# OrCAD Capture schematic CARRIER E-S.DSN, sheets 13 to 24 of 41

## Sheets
13 B4B11
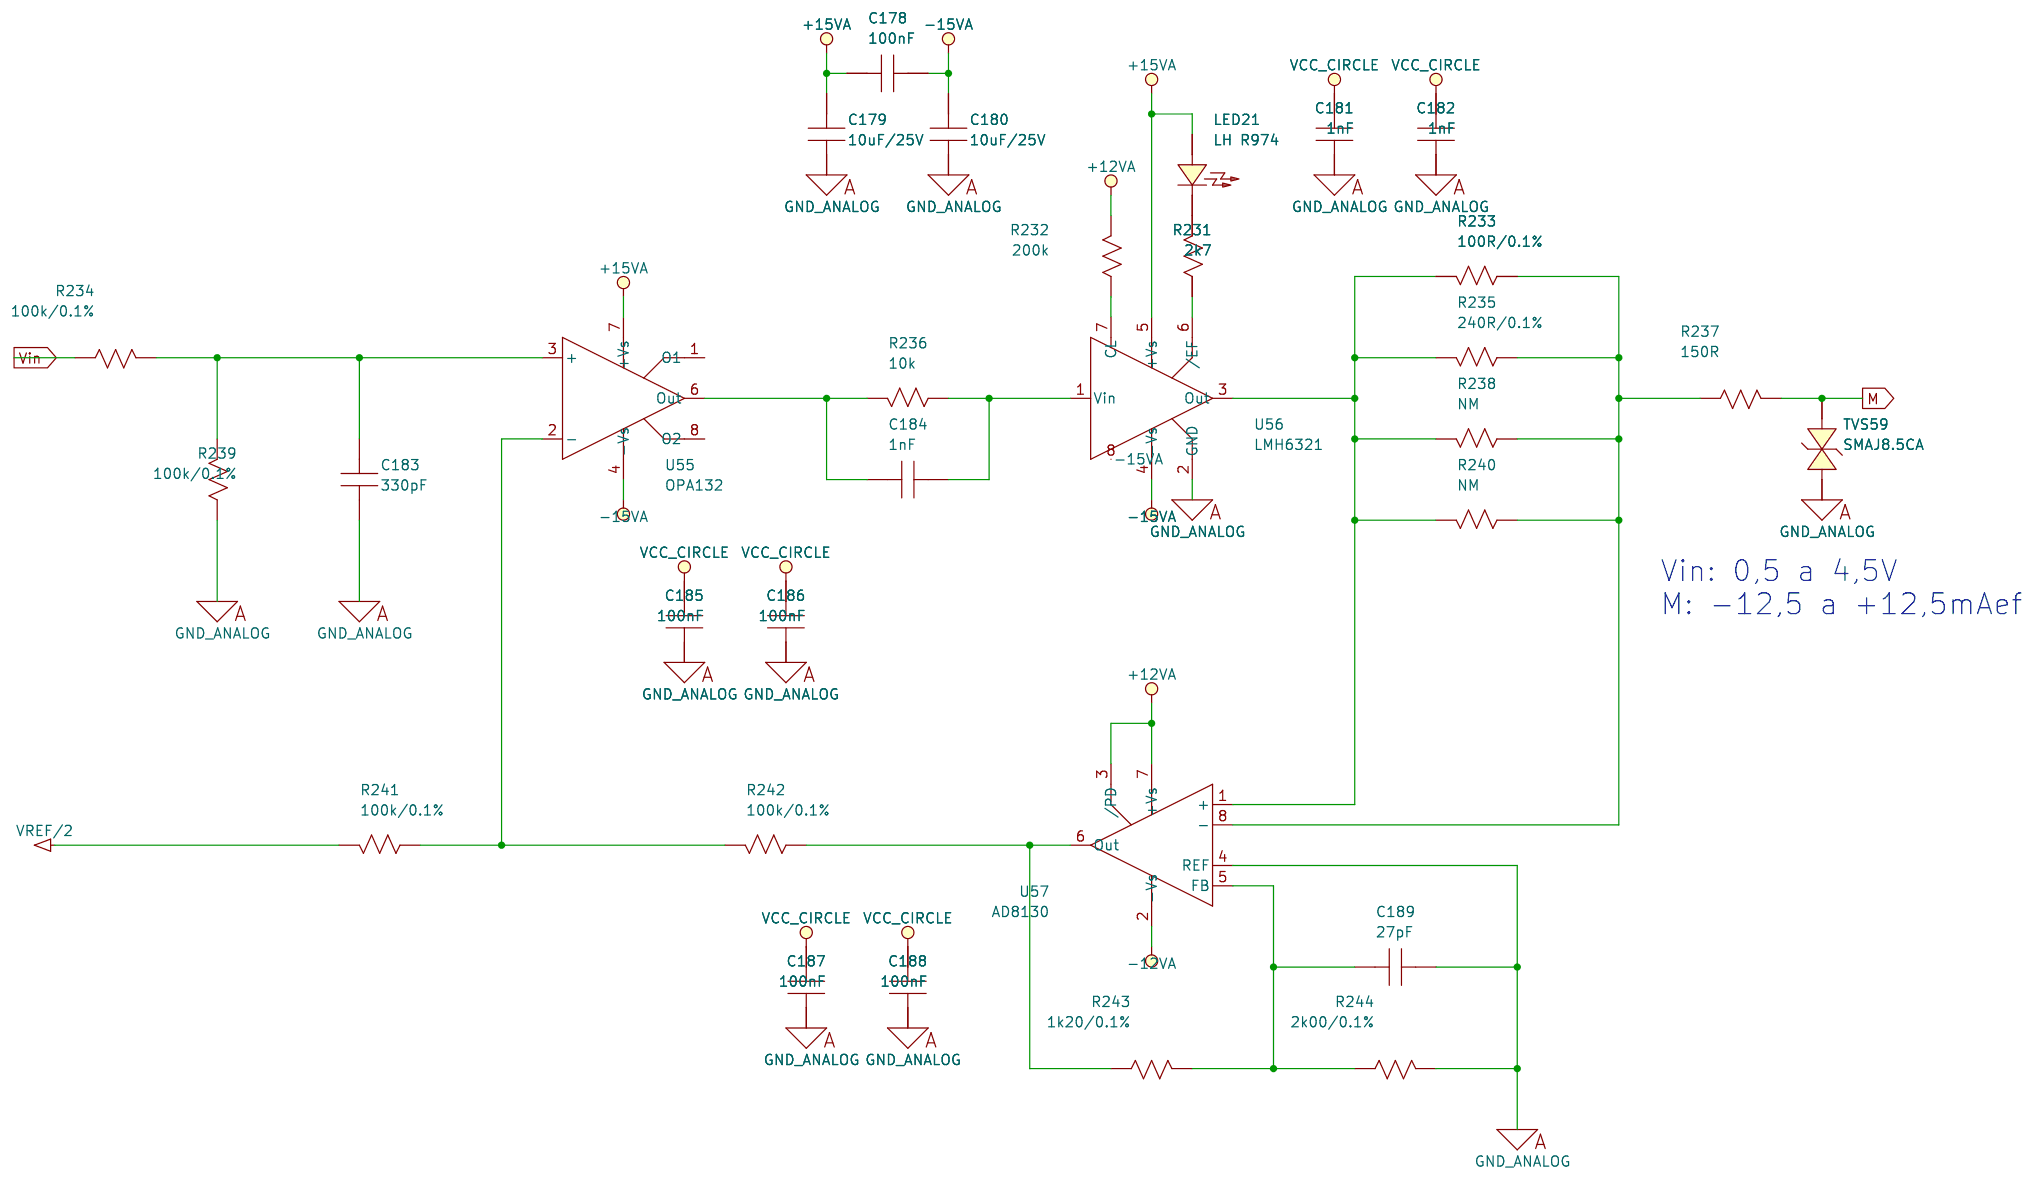
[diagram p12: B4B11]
14 B4B13
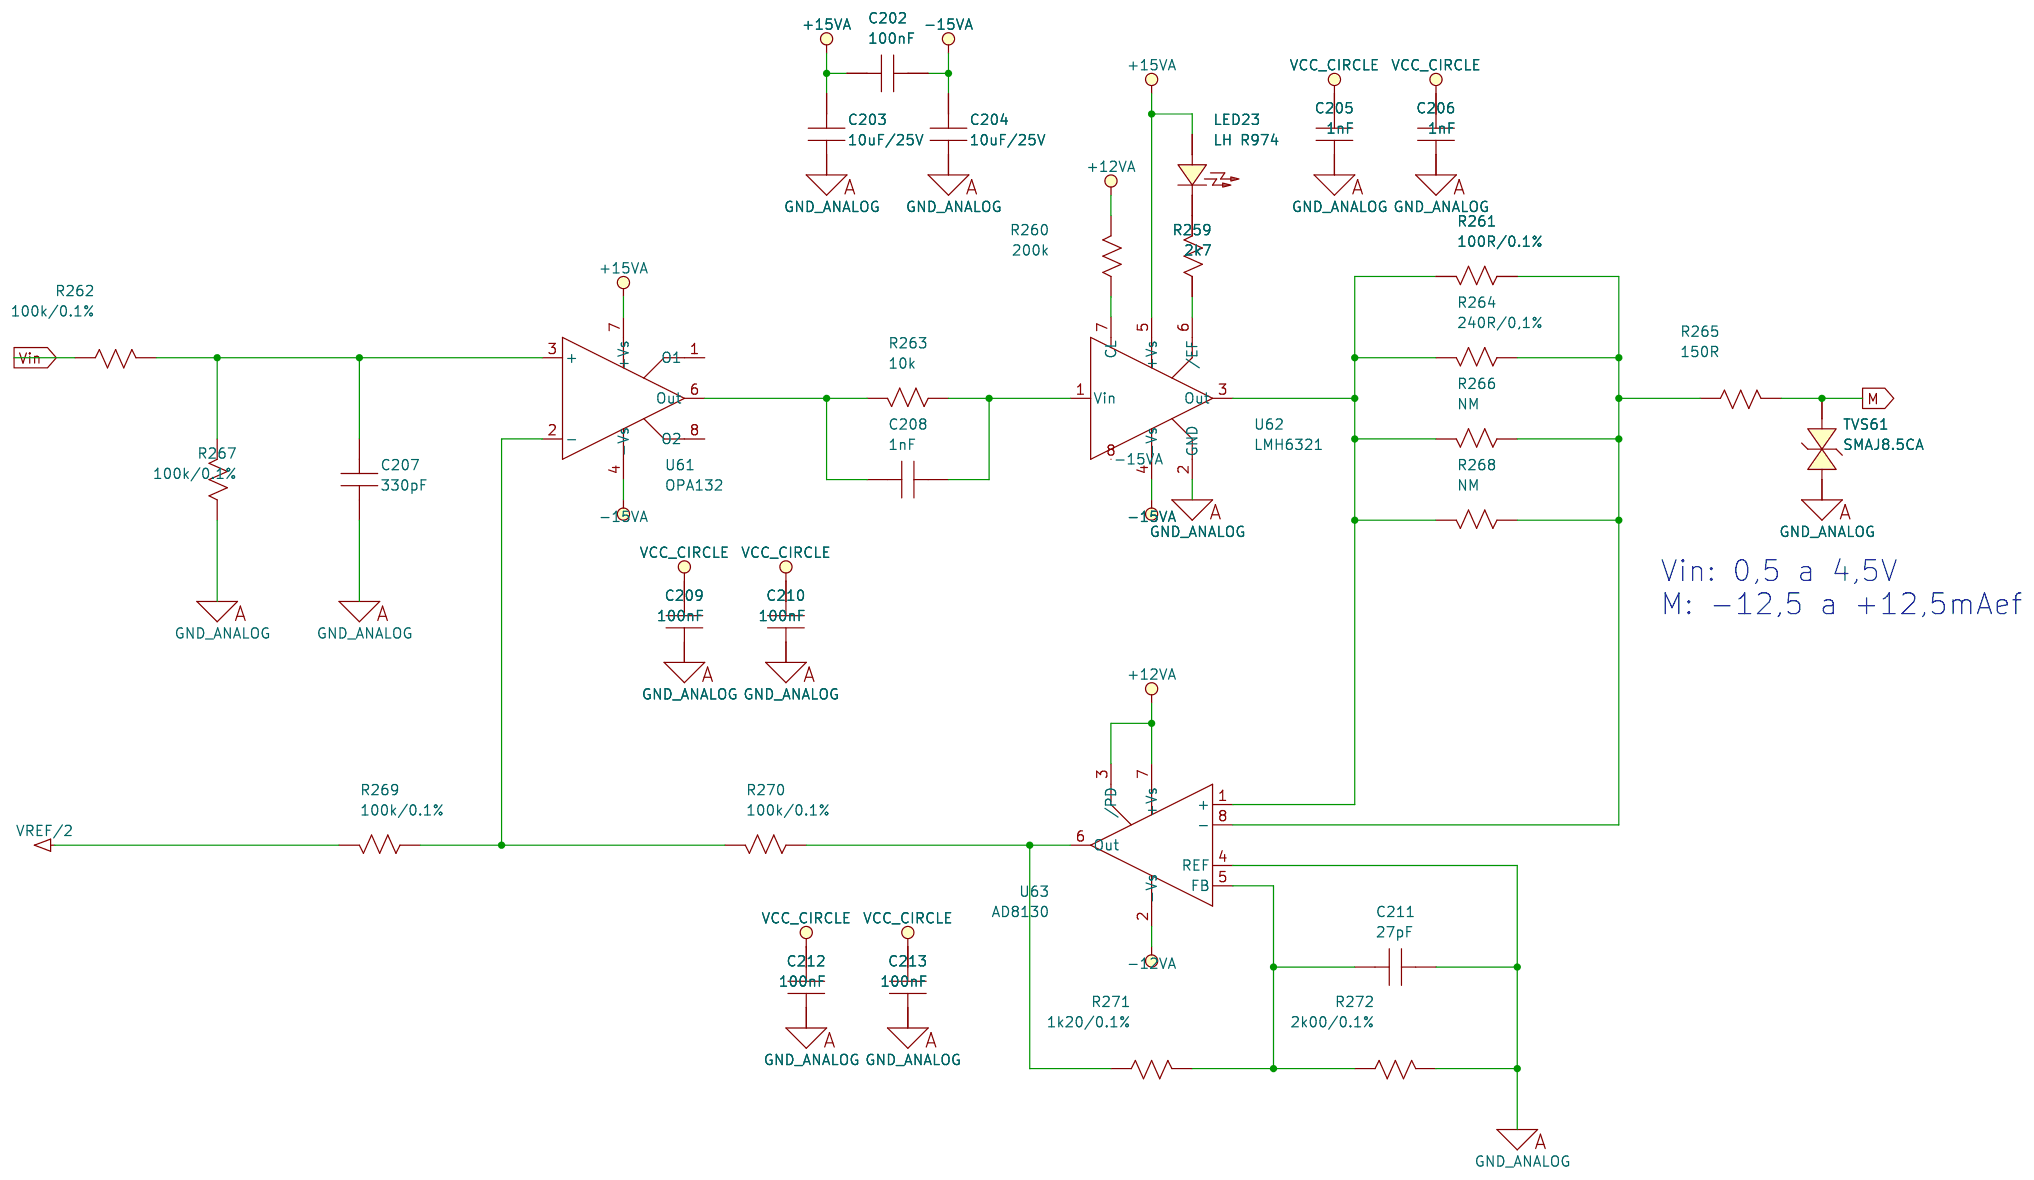
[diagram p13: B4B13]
15 B4B08
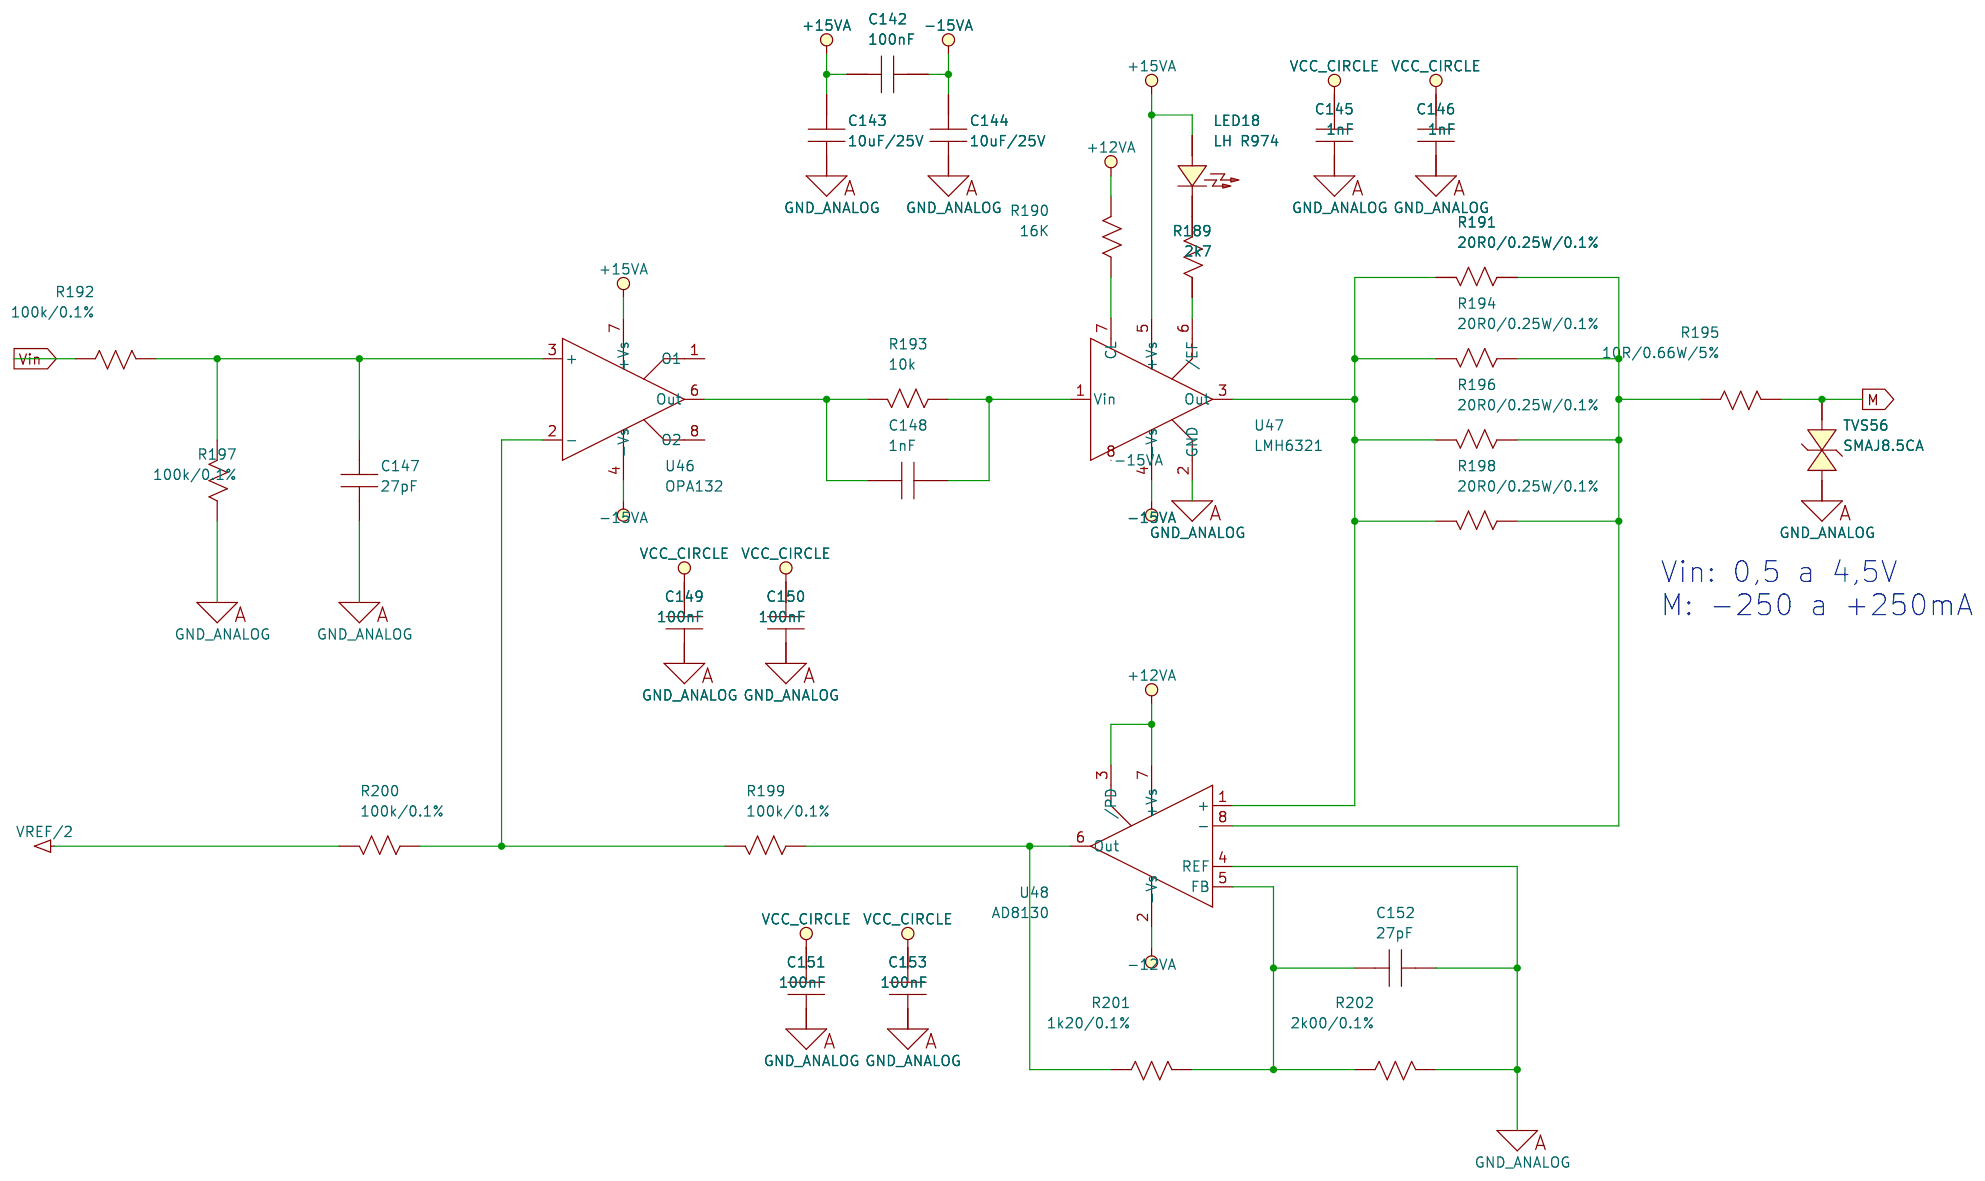
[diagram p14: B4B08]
16 B4B15
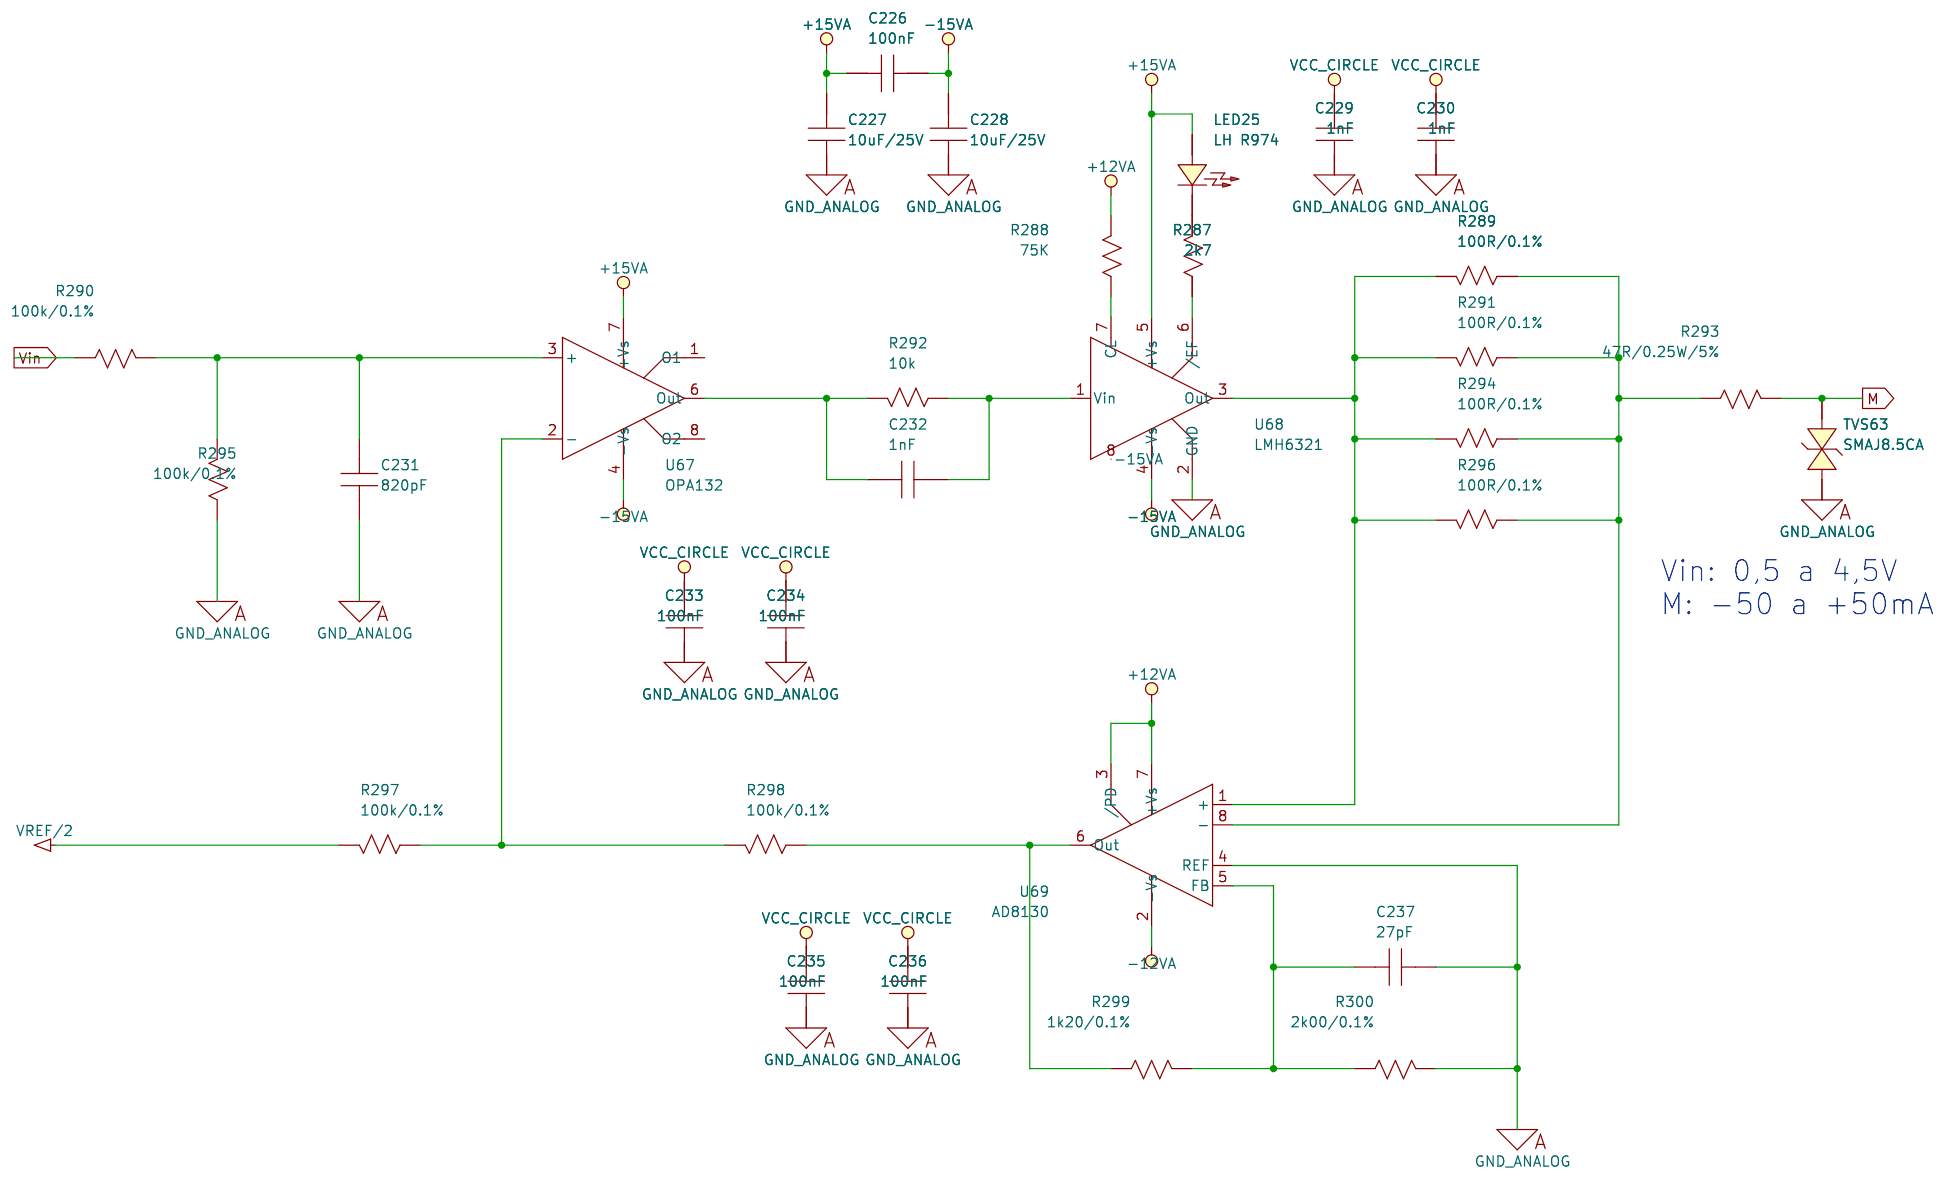
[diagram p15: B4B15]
17 B4B14
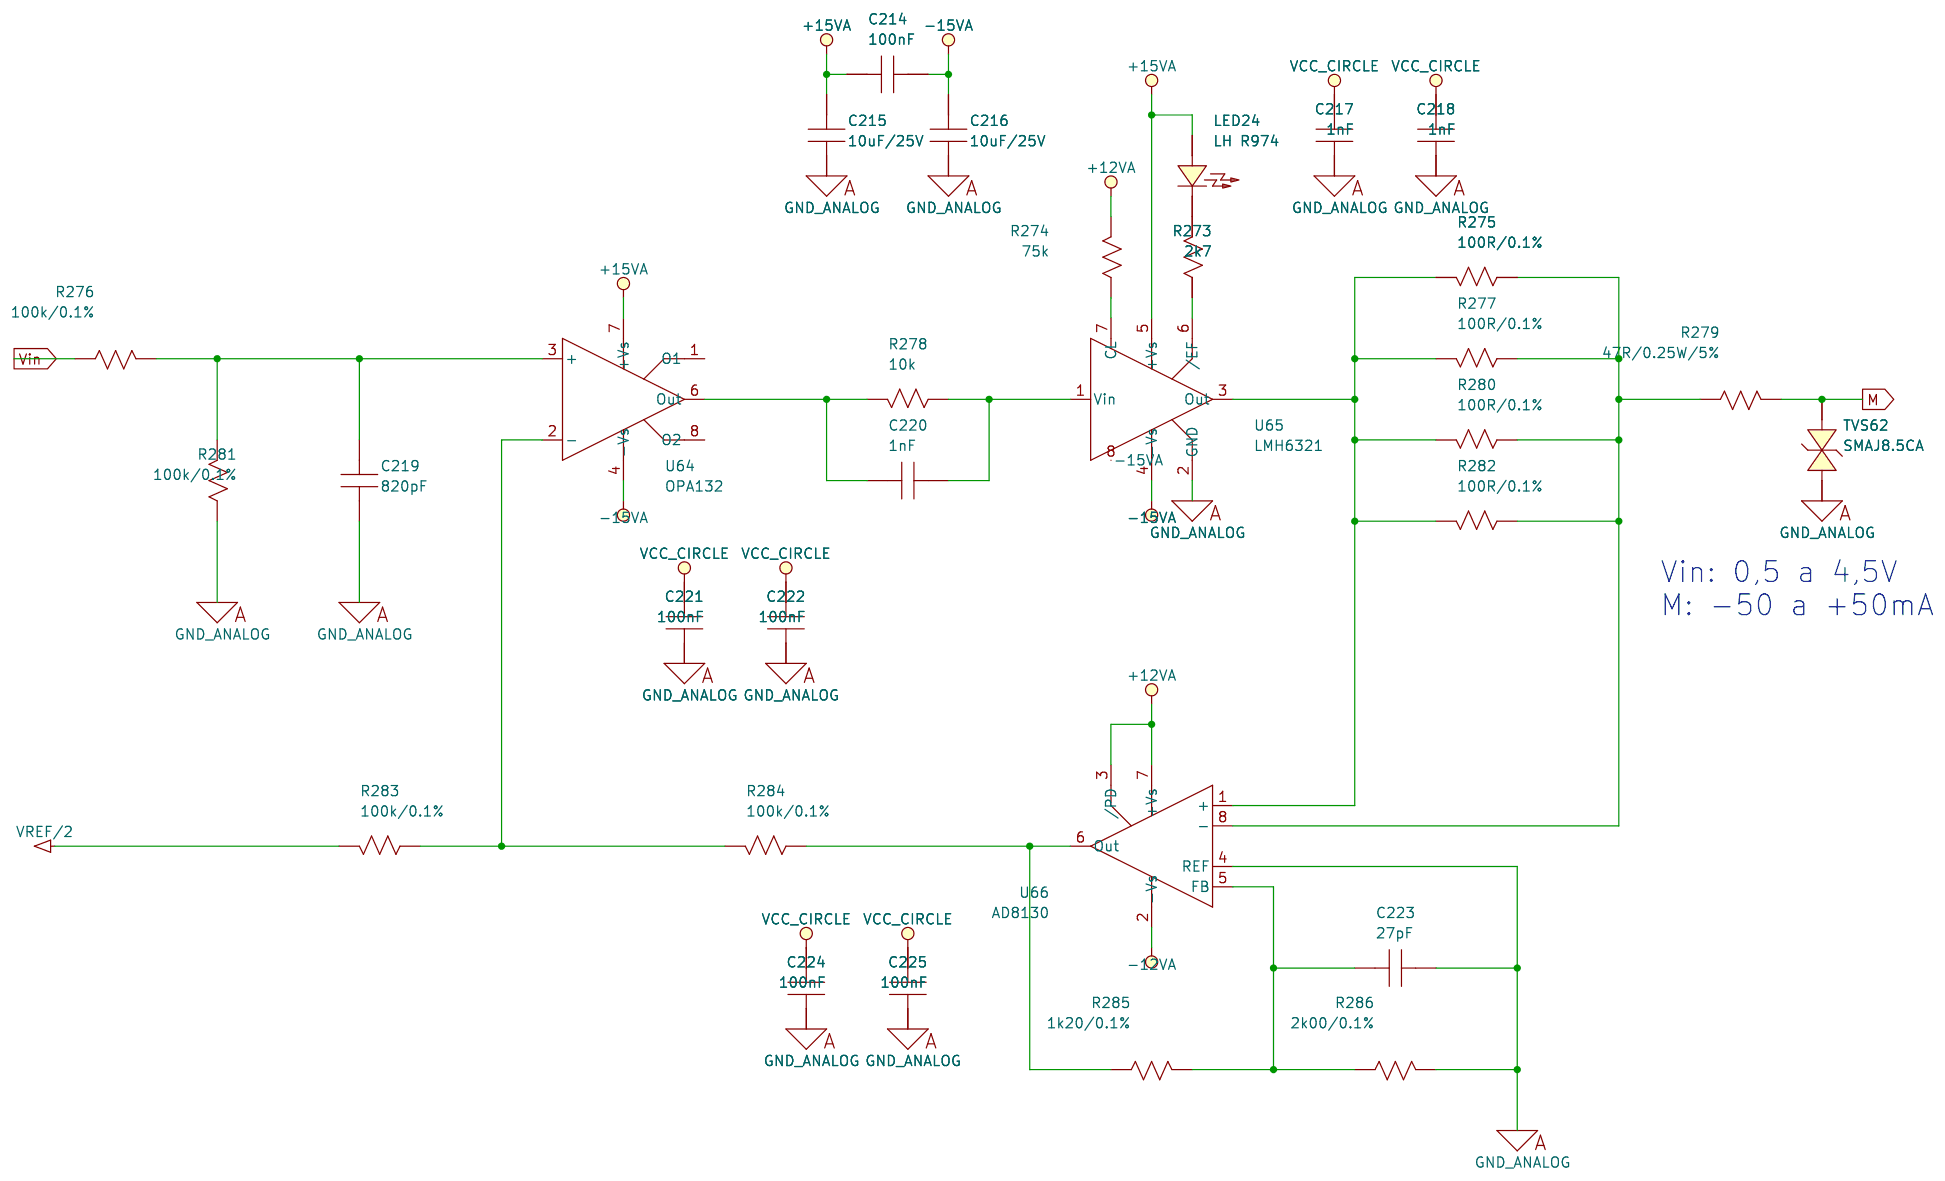
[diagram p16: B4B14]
18 B4B21
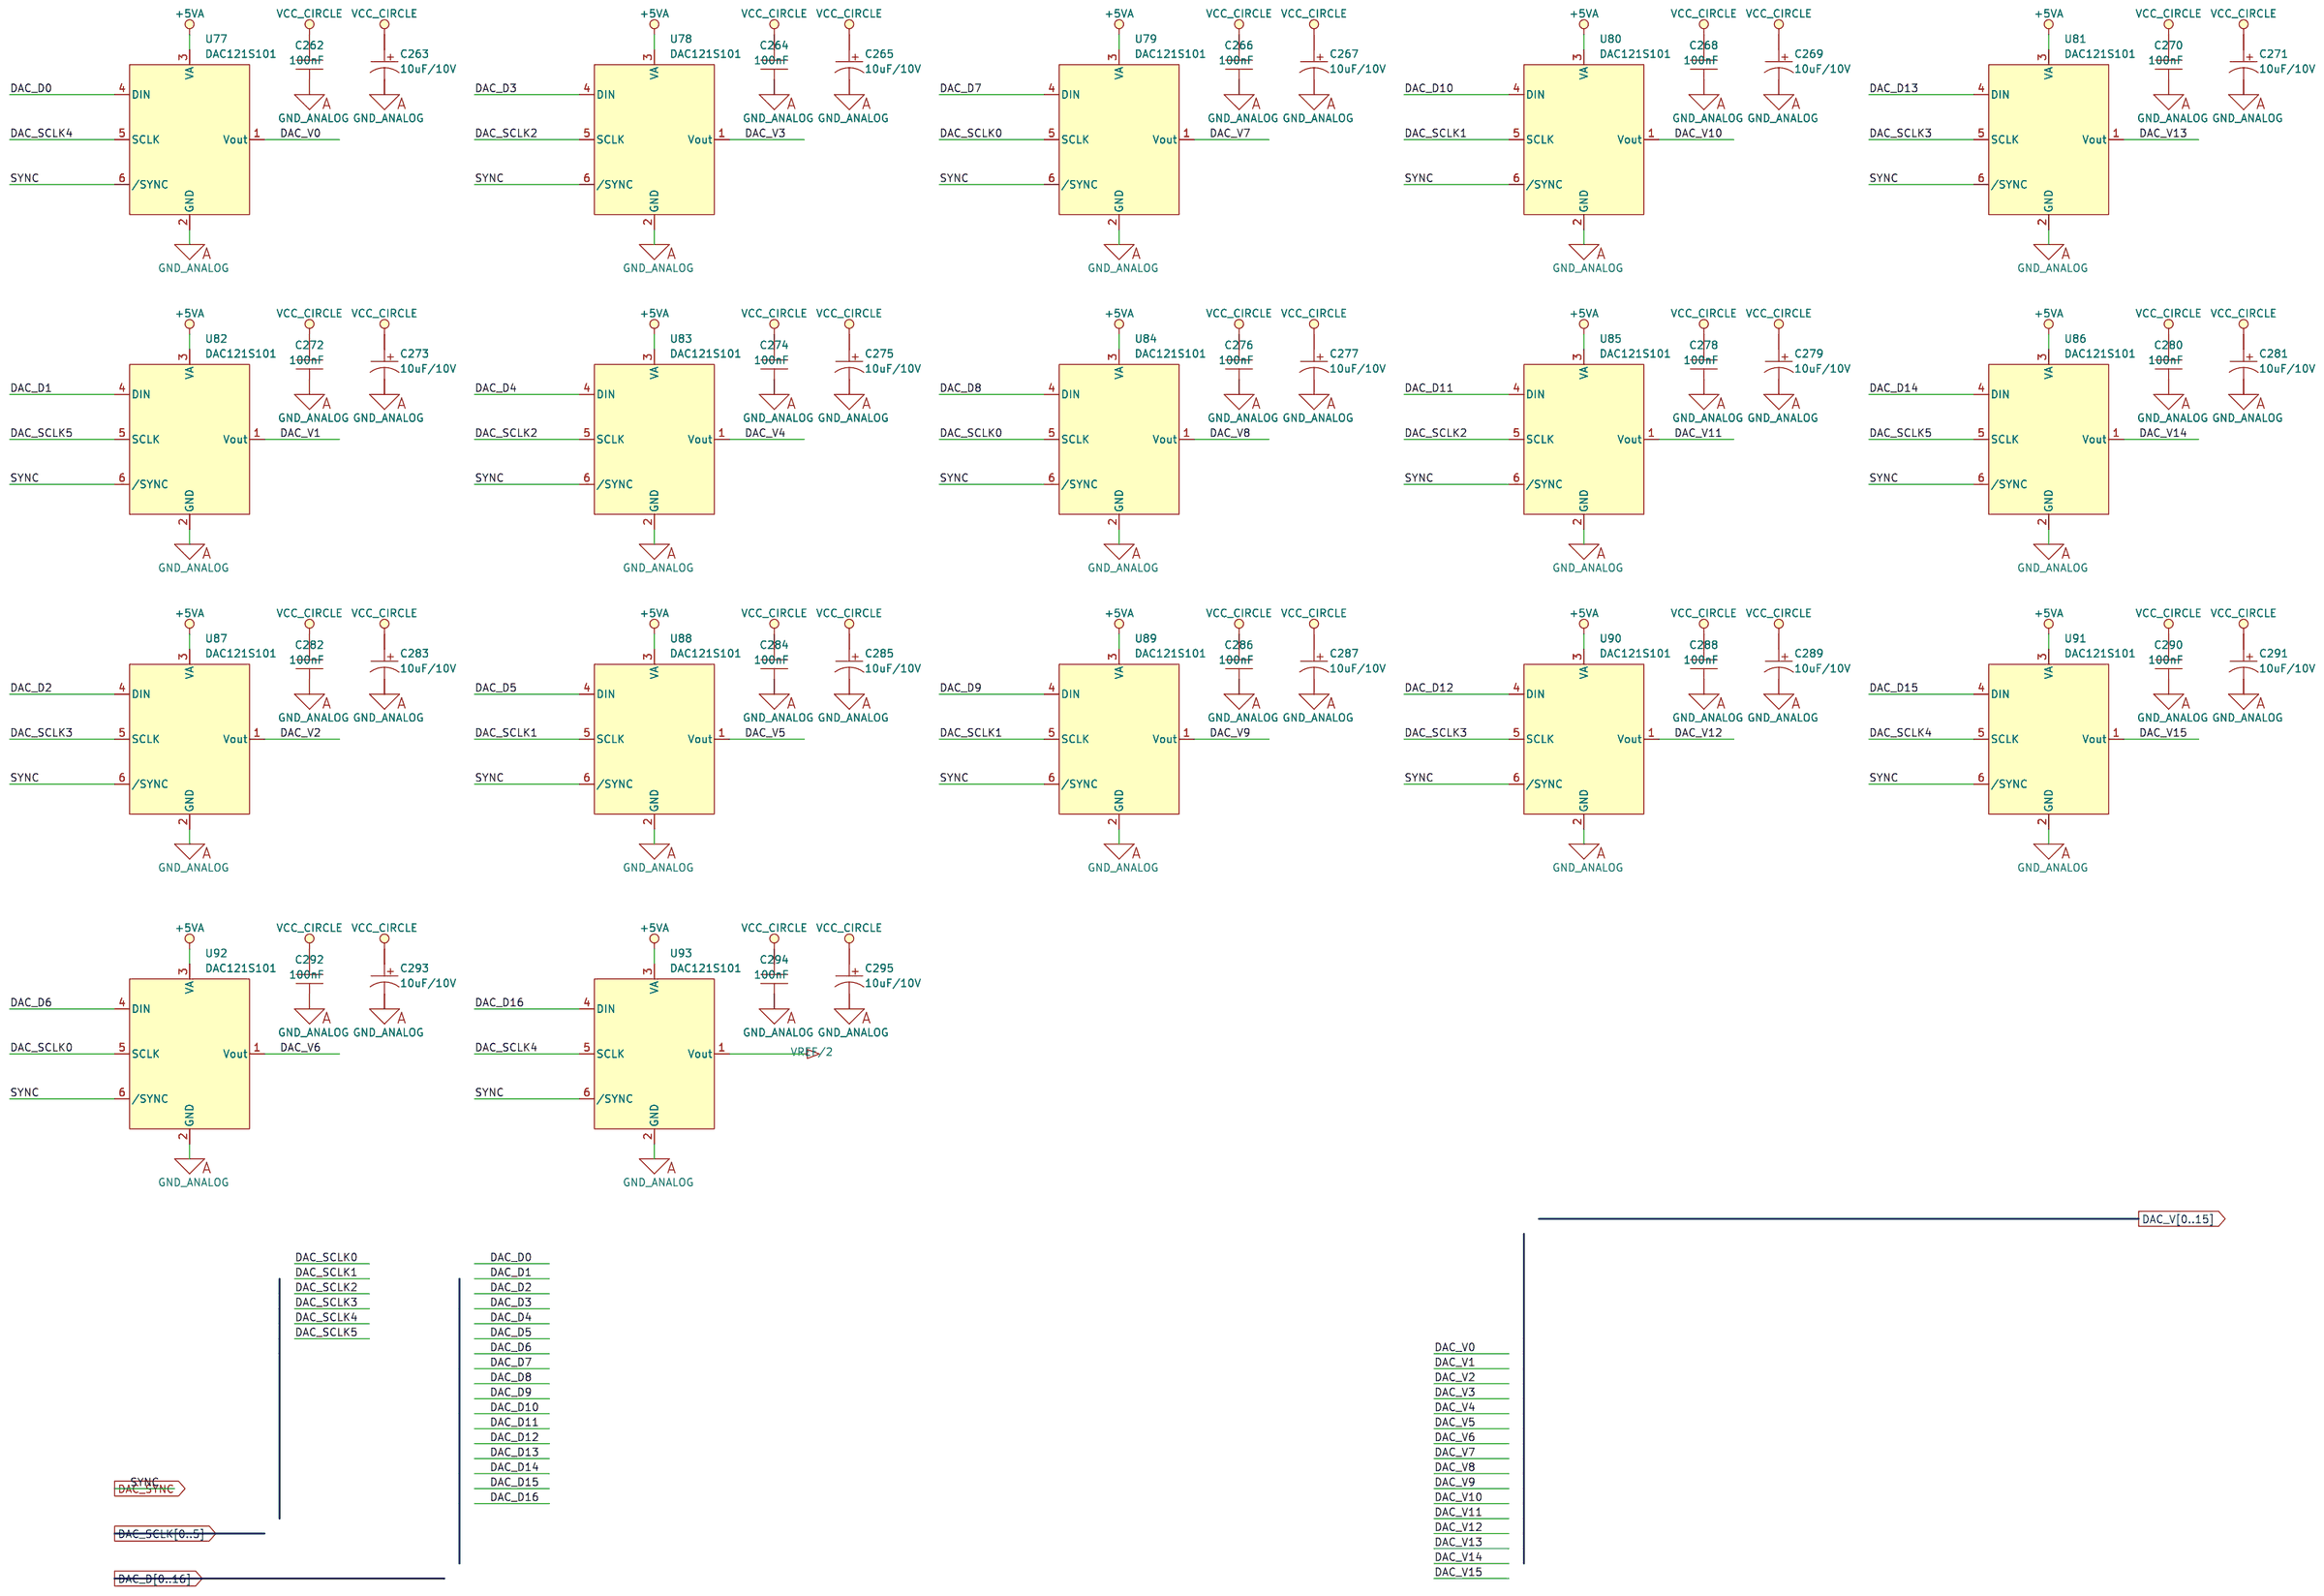
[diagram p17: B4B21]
19 B4B16
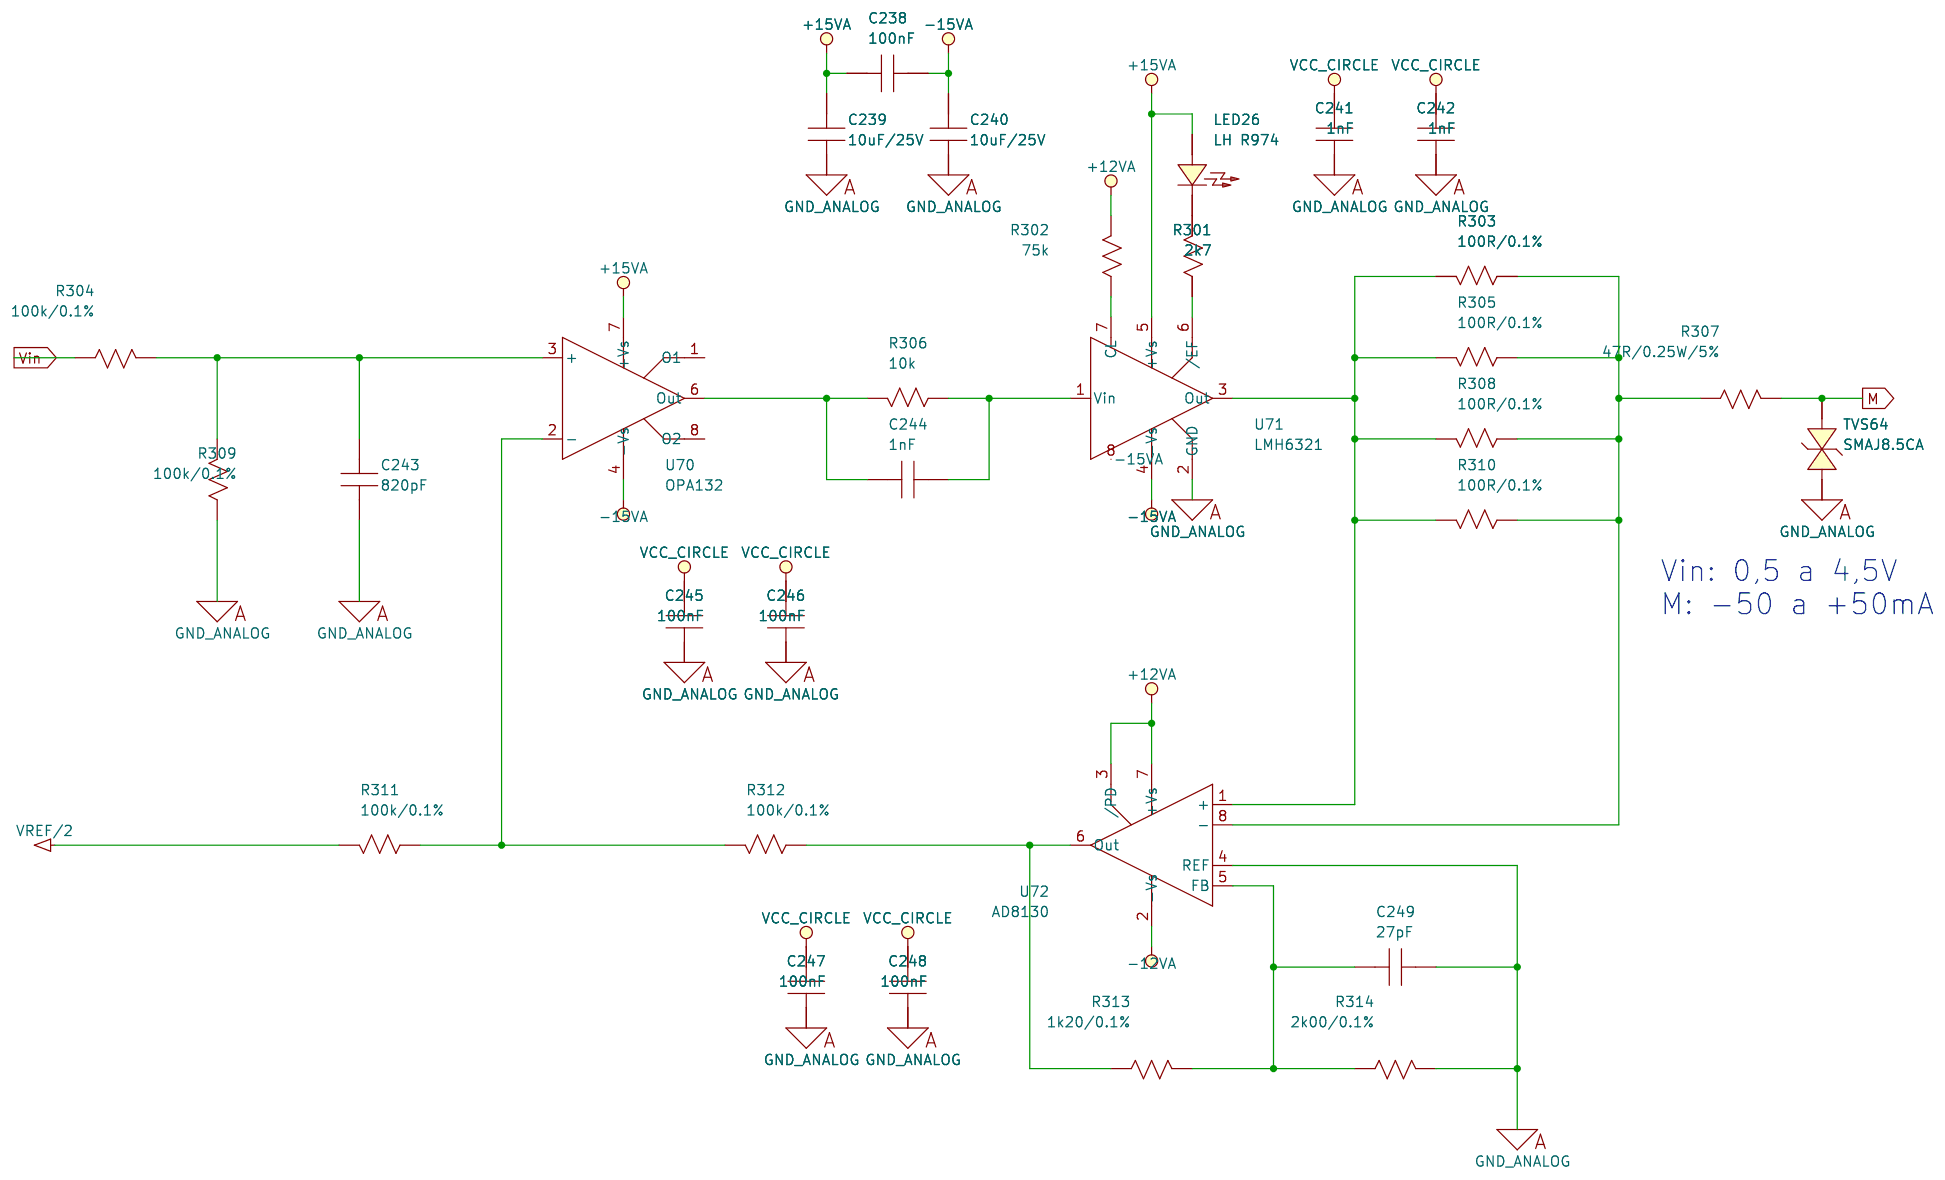
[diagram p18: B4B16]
20 B4B12
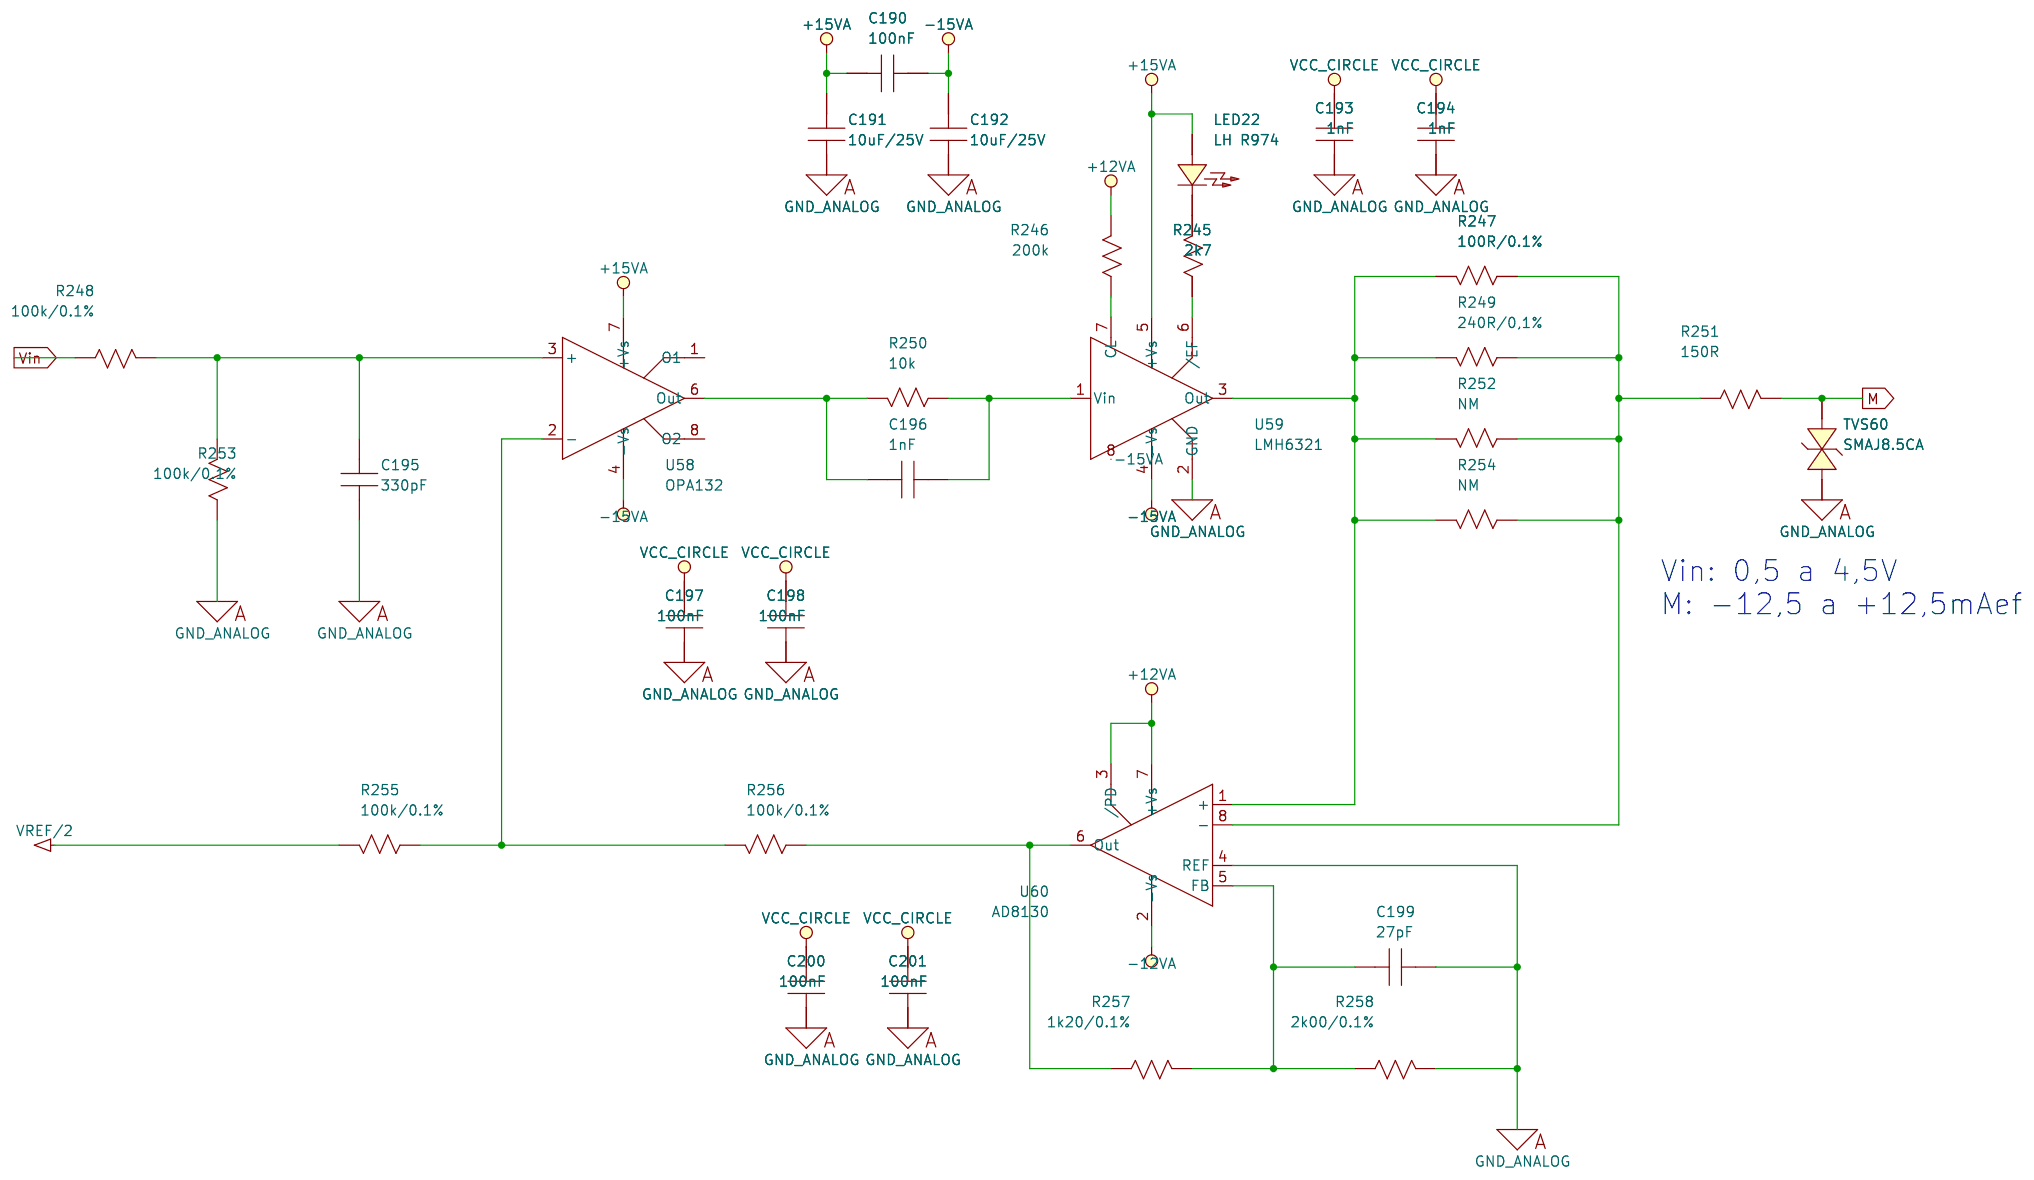
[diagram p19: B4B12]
21 B4B09
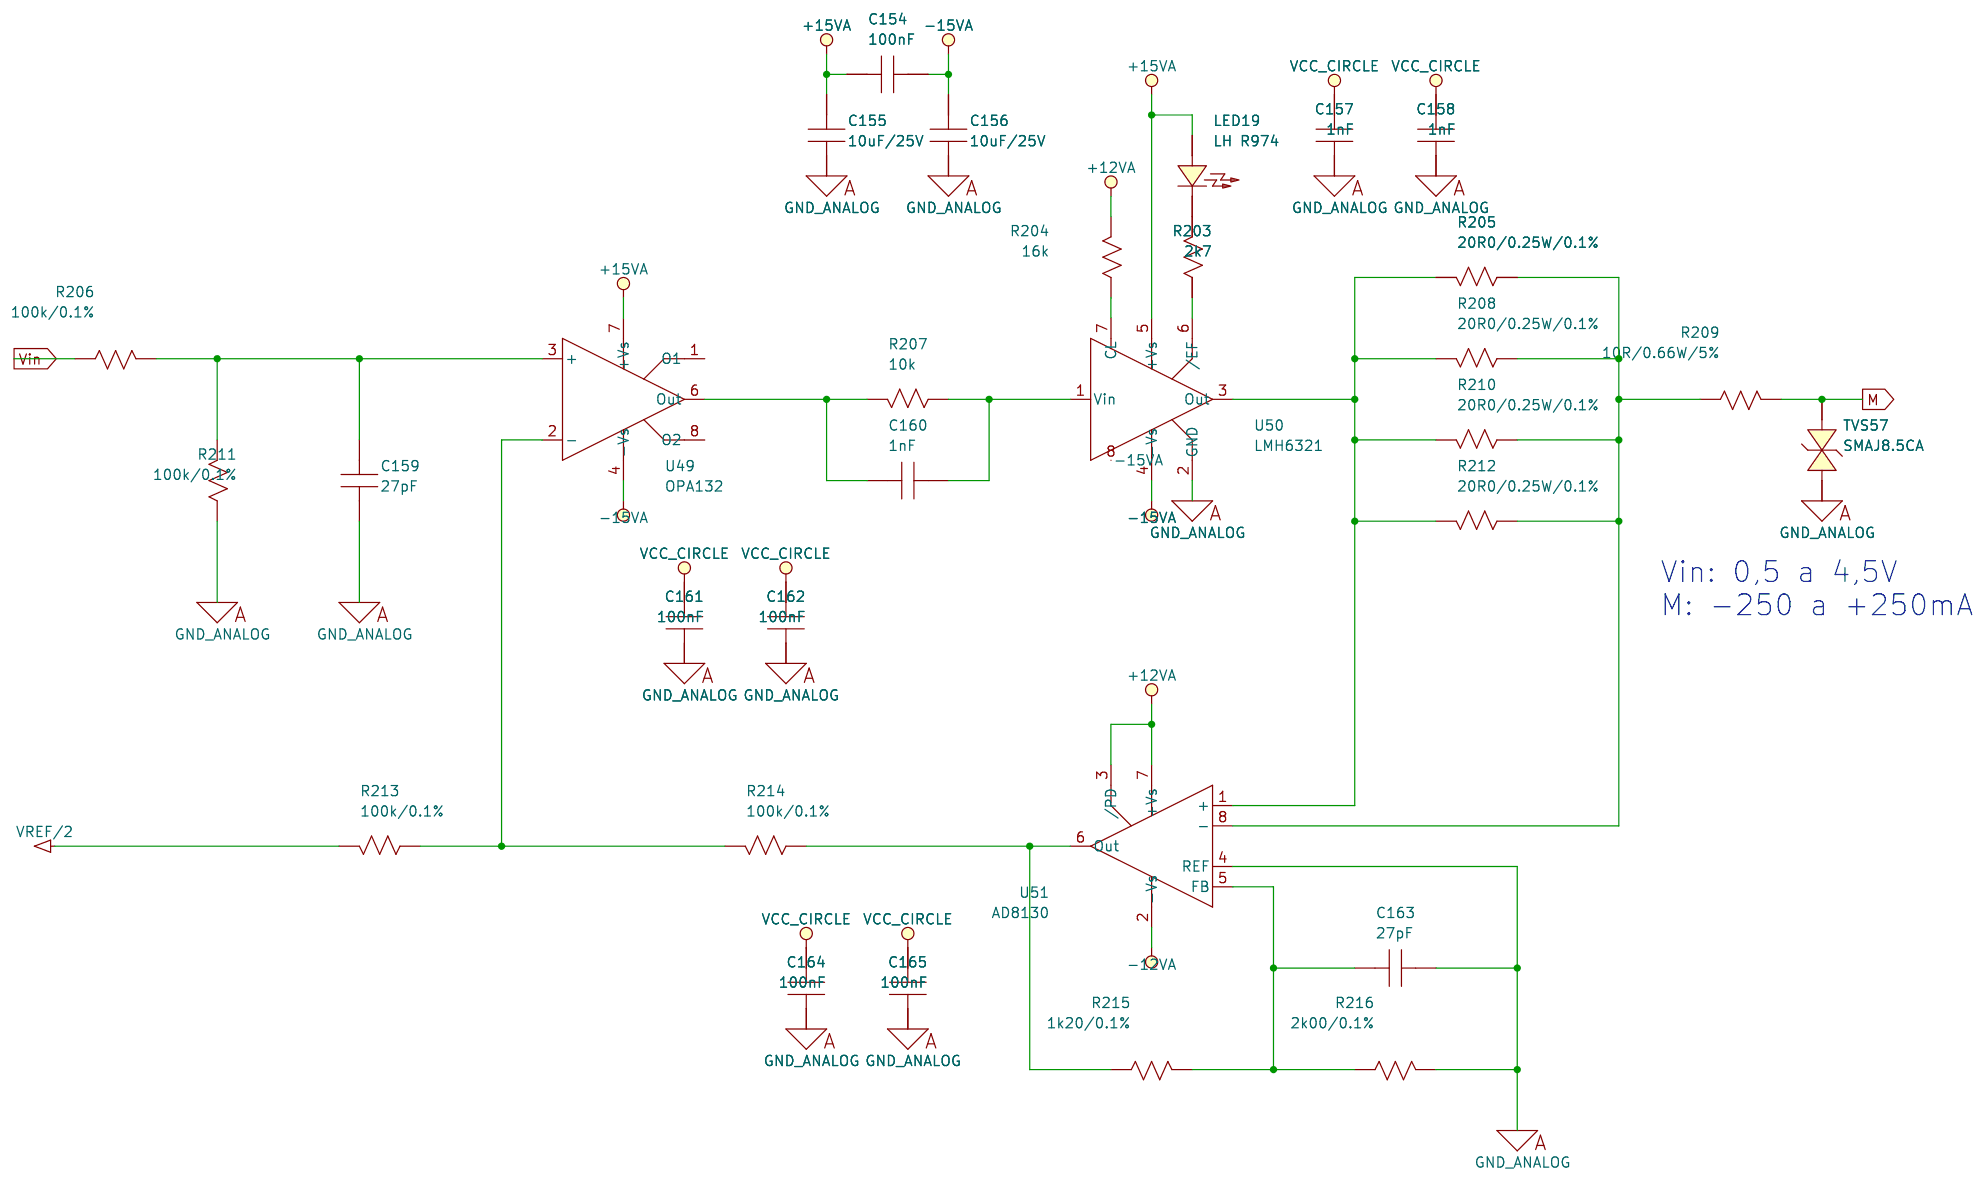
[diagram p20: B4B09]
22 B4B01
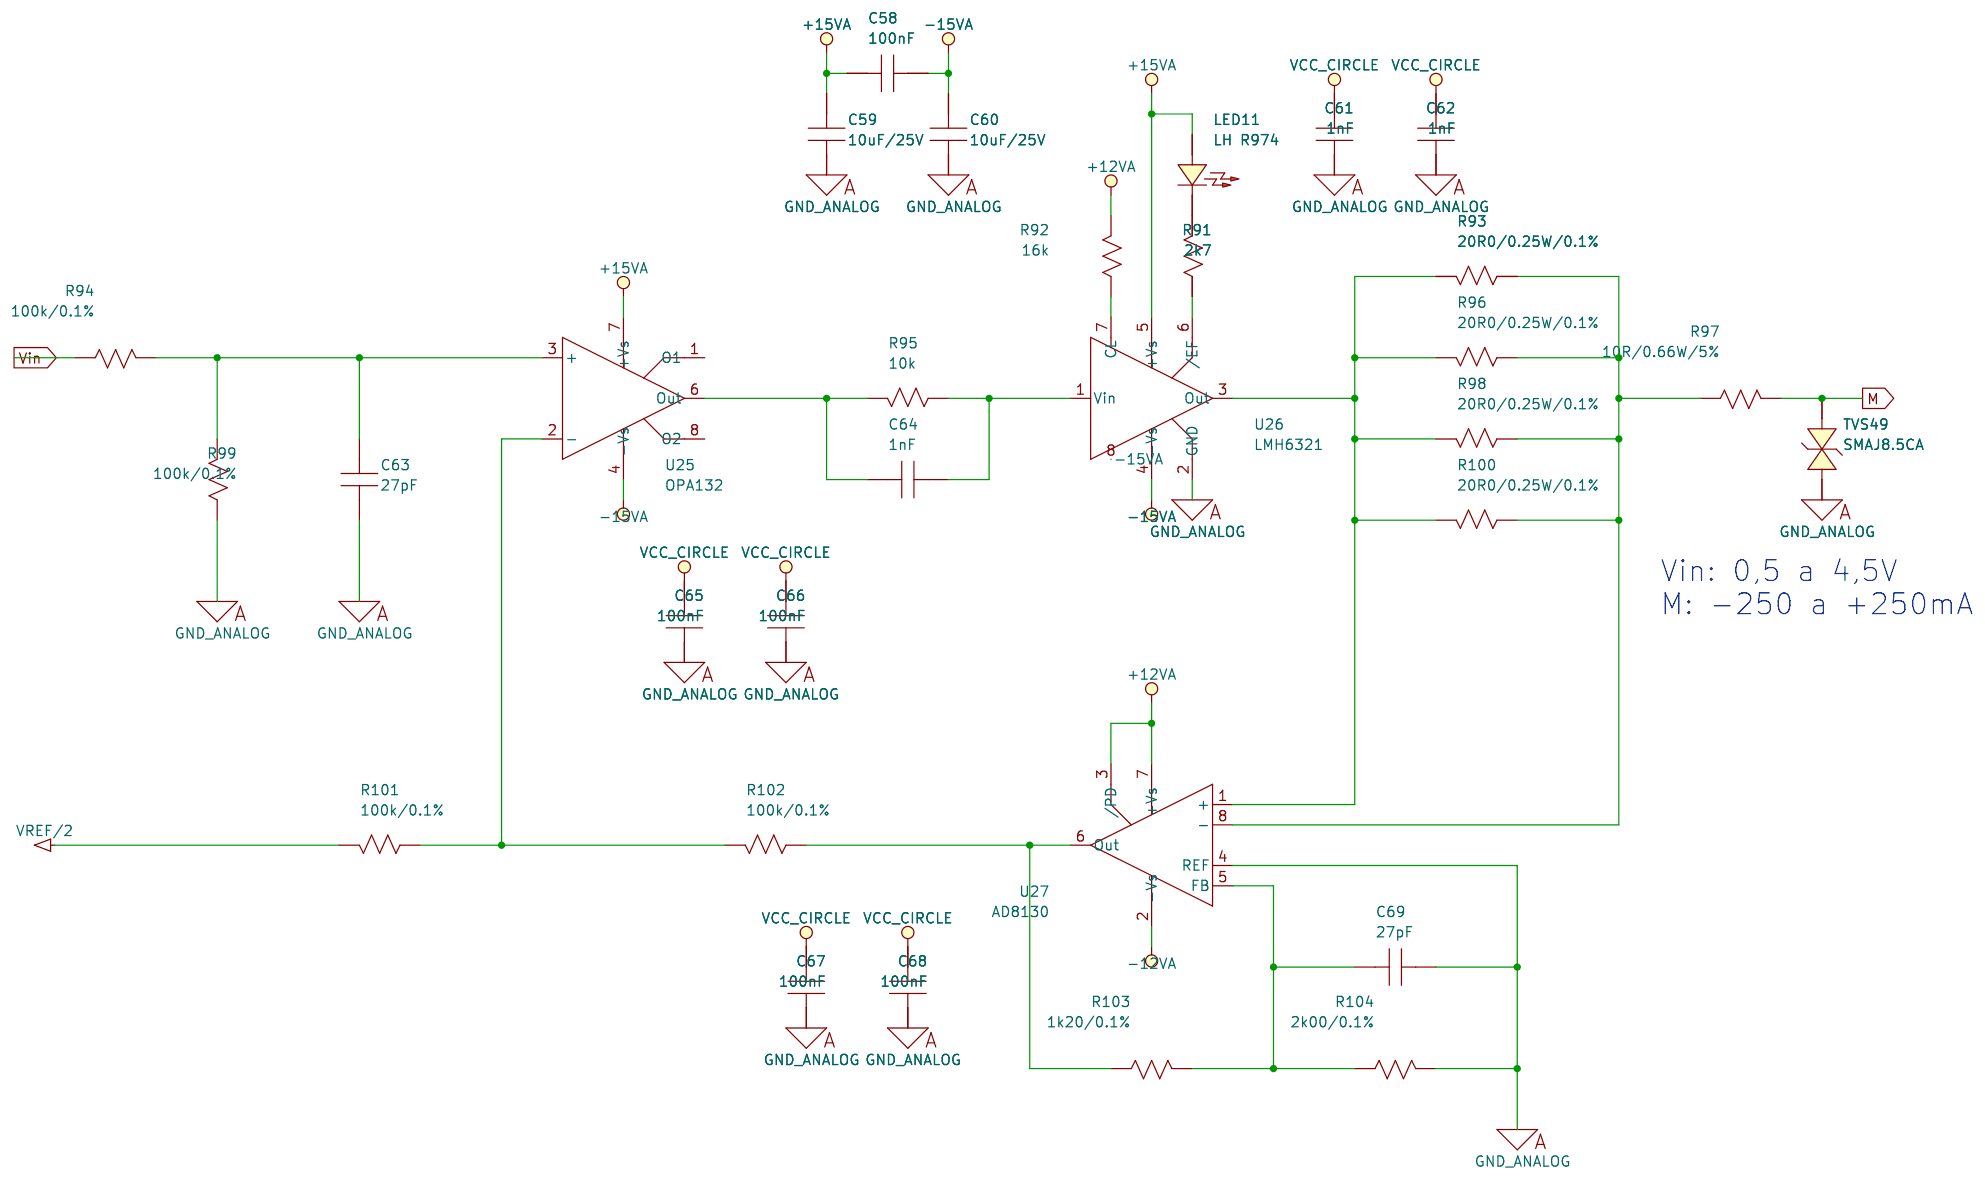
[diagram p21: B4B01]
23 B1: size A4; block Alimentacion
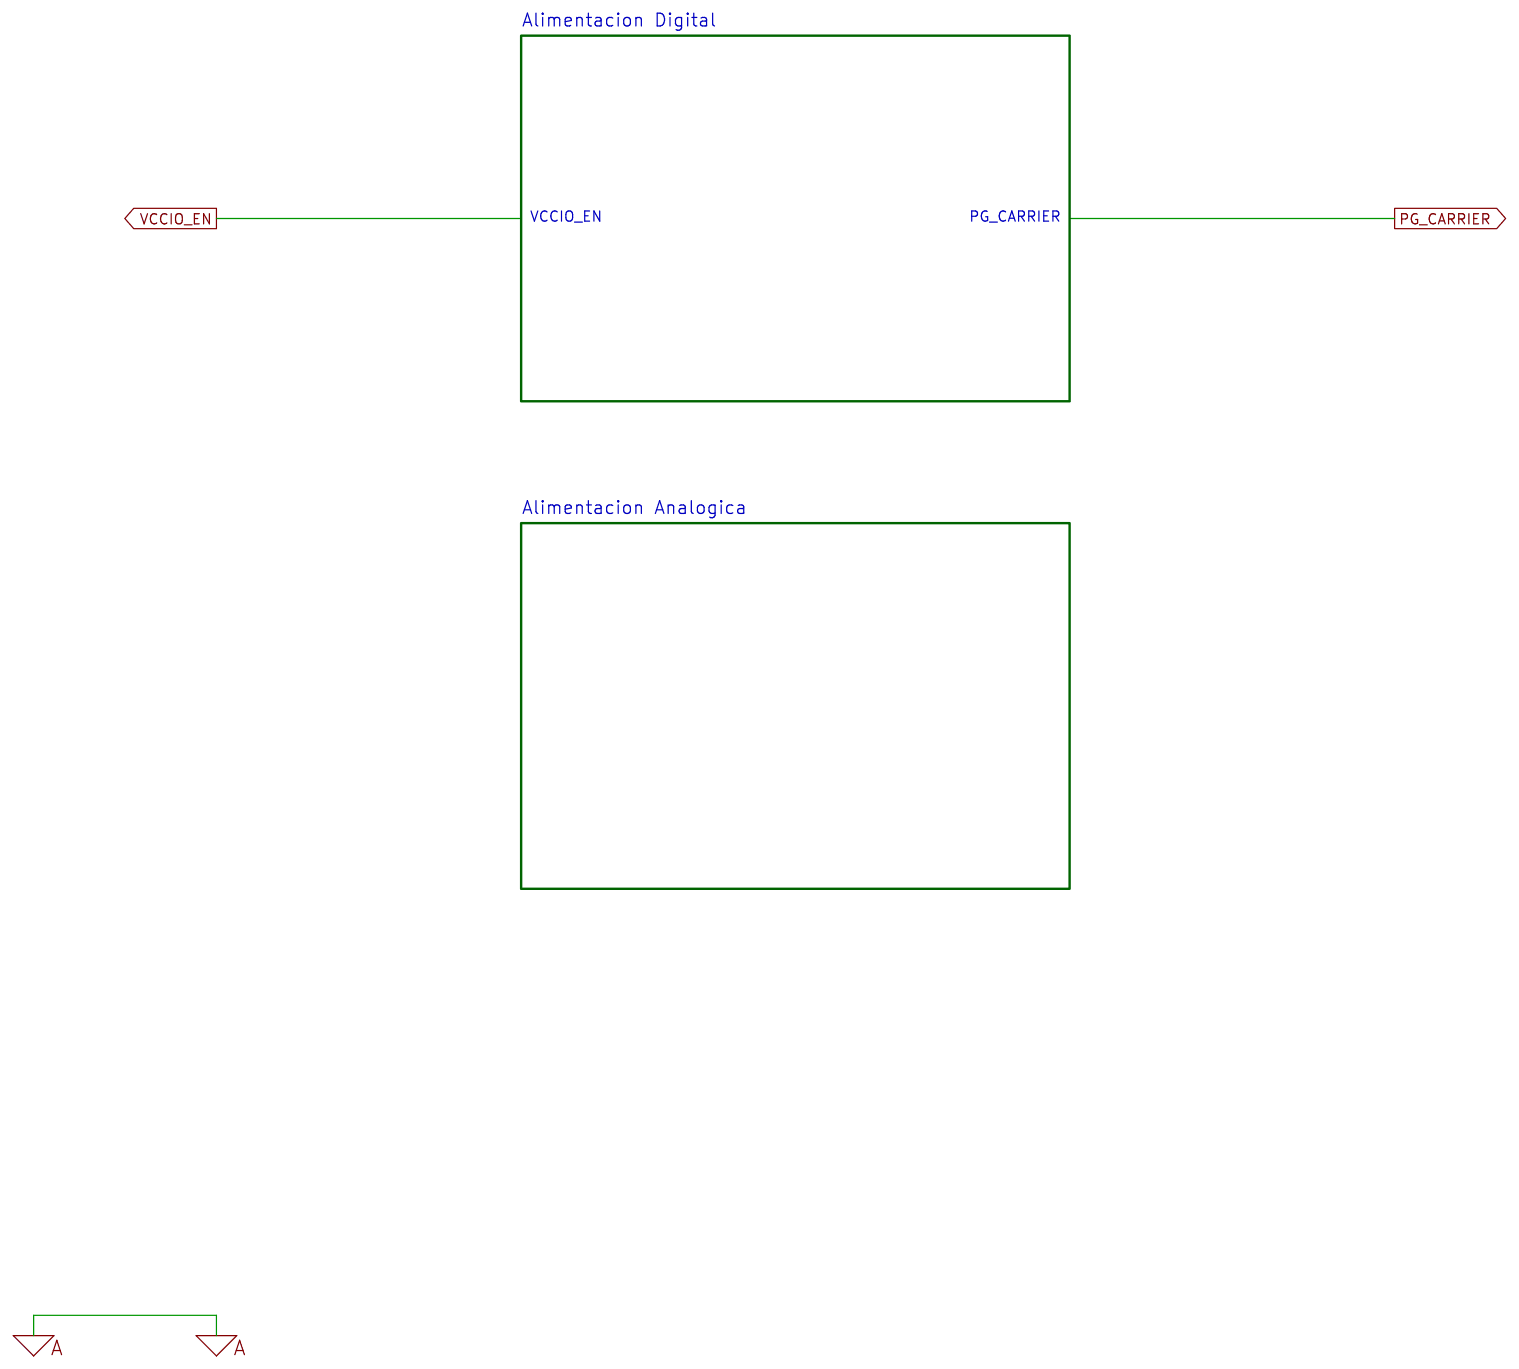
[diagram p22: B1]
24 B1B2: size A4; block Alimentacion/Alimentacion Analogica
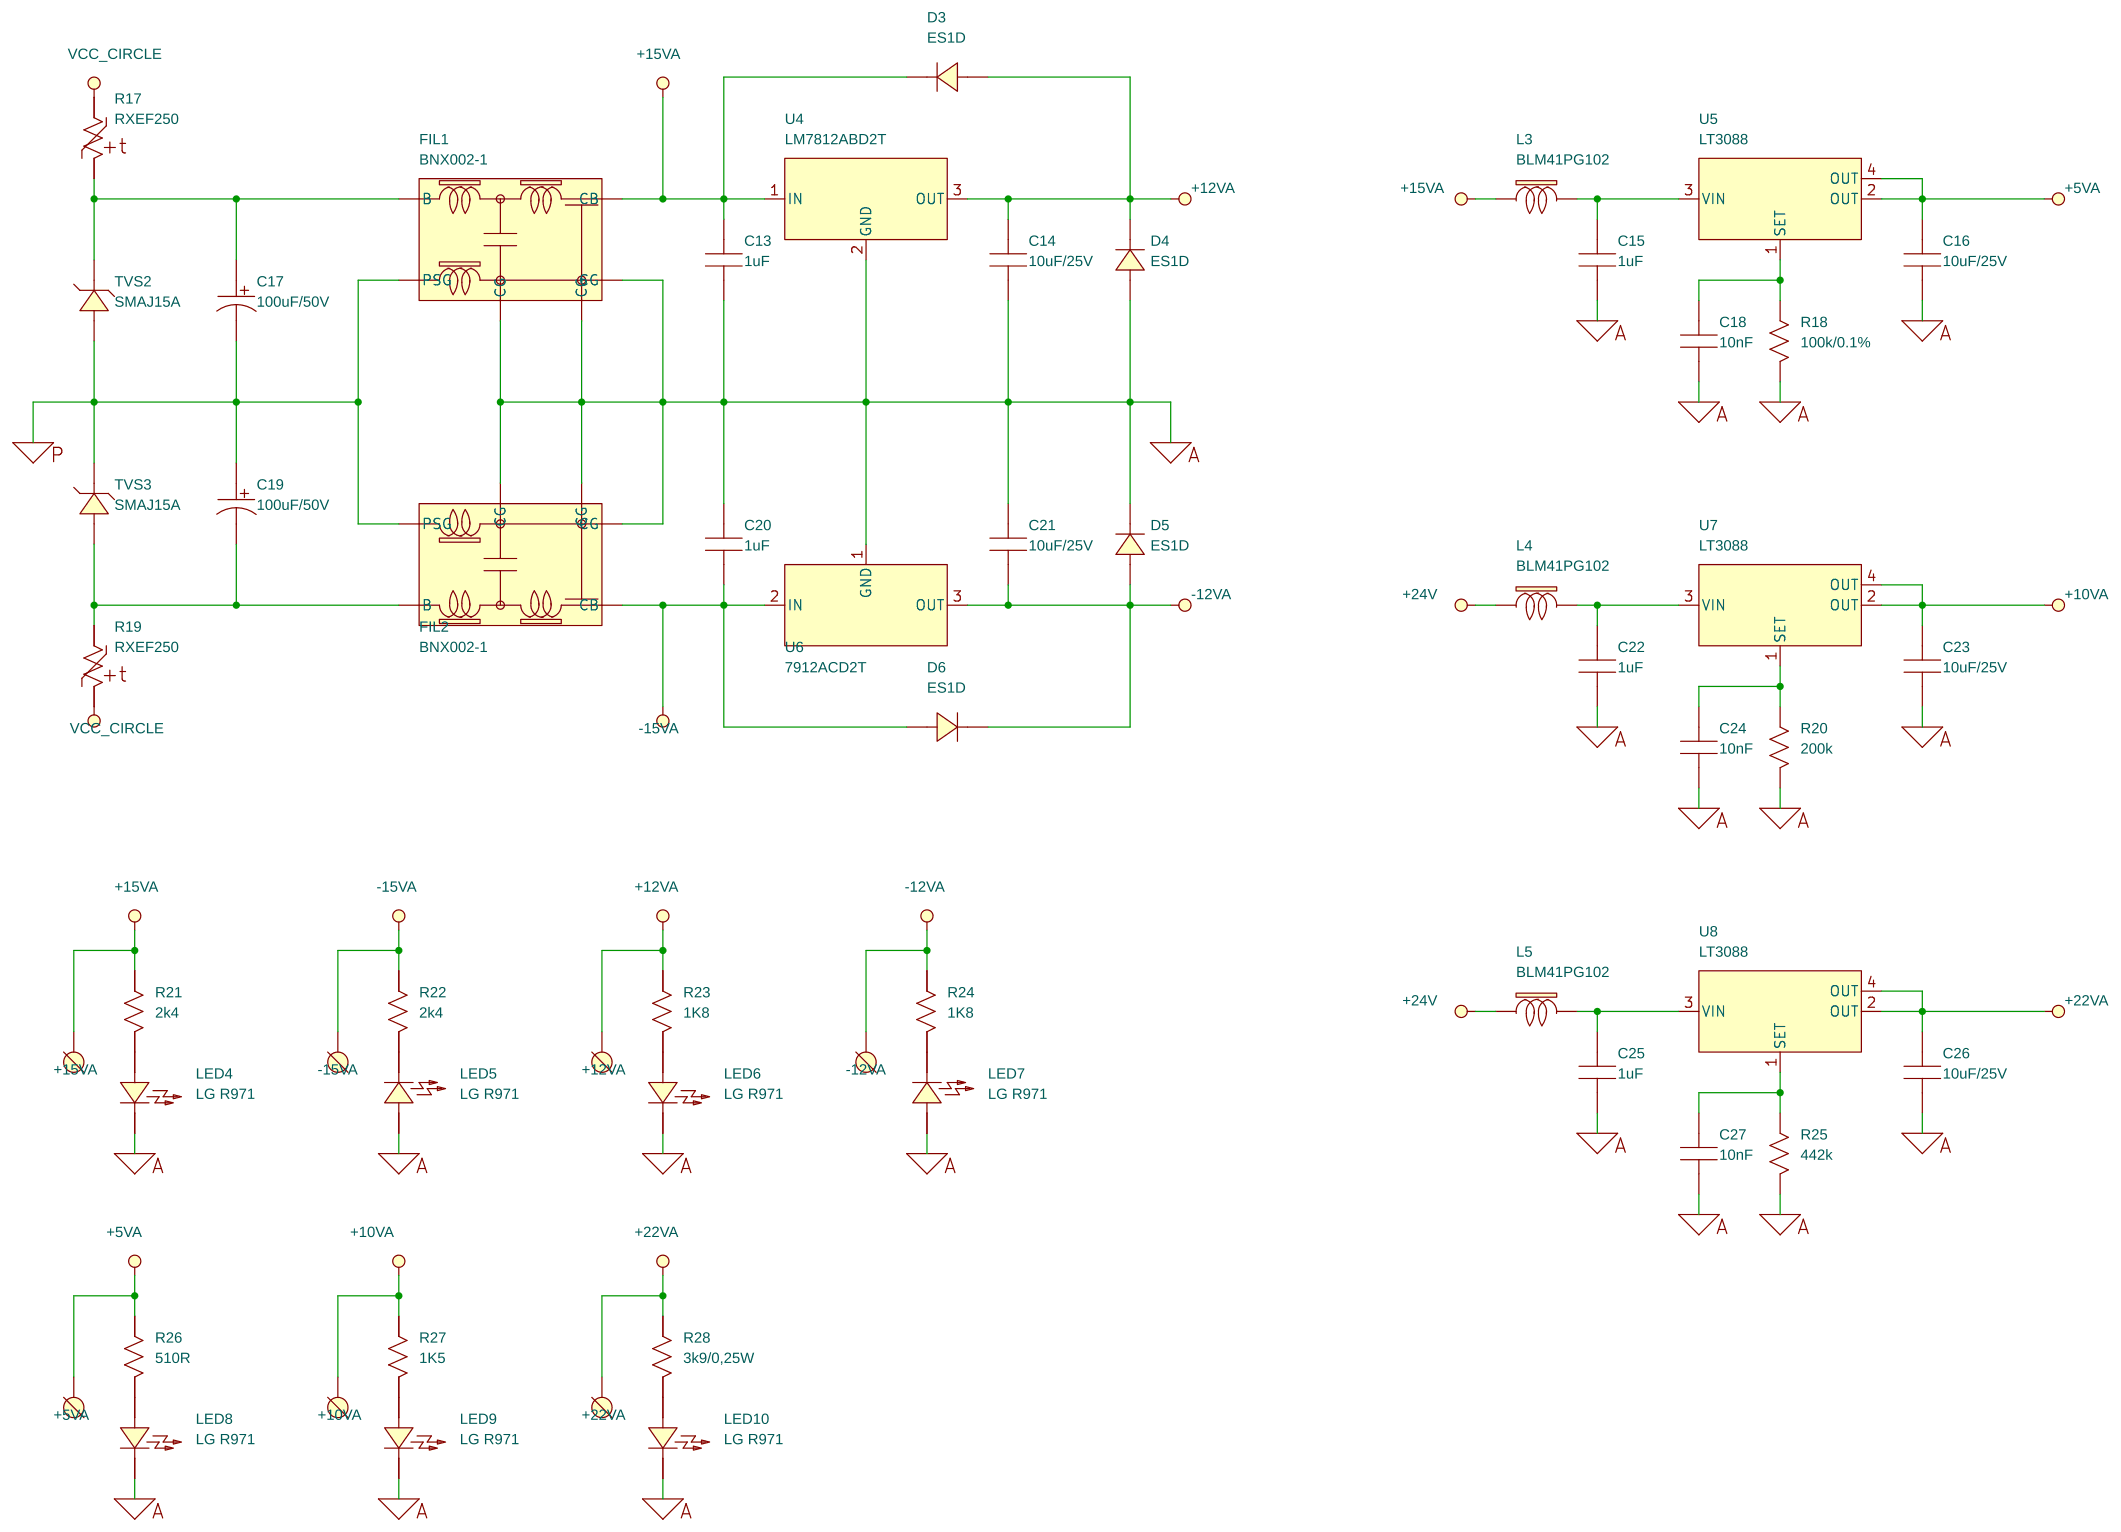
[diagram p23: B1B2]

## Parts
sheet B1B2
+5VA  TEST POINT  [TP/.040/.76]
+10VA  TEST POINT  [TP/.040/.76]
+12VA  TEST POINT  [TP/.040/.76]
+15VA  TEST POINT  [TP/.040/.76]
+22VA  TEST POINT  [TP/.040/.76]
-12VA  TEST POINT  [TP/.040/.76]
-15VA  TEST POINT  [TP/.040/.76]
C13  1uF  [C/SM/1206/IPC-7351 (2005)/NORMAL]
C14  10uF/25V  [C/SM/1210/IPC-7351 (2005)/NORMAL]
C15  1uF  [C/SM/1206/IPC-7351 (2005)/NORMAL]
C16  10uF/25V  [C/SM/1210/IPC-7351 (2005)/NORMAL]
C17  100uF/50V  [CYL/D.400/LS.200/.076/.034/IPC-7351 (2005)/NORMAL]
C18  10nF  [R/SM/0805/IPC-7351 (2005)/NORMAL]
C19  100uF/50V  [CYL/D.400/LS.200/.076/.034/IPC-7351 (2005)/NORMAL]
C20  1uF  [C/SM/1206/IPC-7351 (2005)/NORMAL]
C21  10uF/25V  [C/SM/1210/IPC-7351 (2005)/NORMAL]
C22  1uF  [C/SM/1206/IPC-7351 (2005)/NORMAL]
C23  10uF/25V  [C/SM/1210/IPC-7351 (2005)/NORMAL]
C24  10nF  [R/SM/0805/IPC-7351 (2005)/NORMAL]
C25  1uF  [C/SM/1206/IPC-7351 (2005)/NORMAL]
C26  10uF/25V  [C/SM/1210/IPC-7351 (2005)/NORMAL]
C27  10nF  [R/SM/0805/IPC-7351 (2005)/NORMAL]
D3  ES1D  [SM/DO214AC/IPC-7351 (2005)/NORMAL]
D4  ES1D  [SM/DO214AC/IPC-7351 (2005)/NORMAL]
D5  ES1D  [SM/DO214AC/IPC-7351 (2005)/NORMAL]
D6  ES1D  [SM/DO214AC/IPC-7351 (2005)/NORMAL]
FIL1  BNX002-1  [BNX002-01]
FIL2  BNX002-1  [BNX002-01]
L3  BLM41PG102  [L/SM/CHIP/1806/IPC-7351 (2005)/NORMAL]
L4  BLM41PG102  [L/SM/CHIP/1806/IPC-7351 (2005)/NORMAL]
L5  BLM41PG102  [L/SM/CHIP/1806/IPC-7351 (2005)/NORMAL]
LED4  LG R971  [LED/SM/0805/IPC-7351 (2005)/NORMAL]
LED5  LG R971  [LED/SM/0805/IPC-7351 (2005)/NORMAL]
LED6  LG R971  [LED/SM/0805/IPC-7351 (2005)/NORMAL]
LED7  LG R971  [LED/SM/0805/IPC-7351 (2005)/NORMAL]
LED8  LG R971  [LED/SM/0805/IPC-7351 (2005)/NORMAL]
LED9  LG R971  [LED/SM/0805/IPC-7351 (2005)/NORMAL]
LED10  LG R971  [LED/SM/0805/IPC-7351 (2005)/NORMAL]
R17  RXEF250  [DISC/.400X.080/LS.820X.150/.076/.040/IPC-7351 (2005)/NORMAL]
R18  100k/0.1%  [R/SM/0805/IPC-7351 (2005)/NORMAL]
R19  RXEF250  [DISC/.400X.080/LS.820X.150/.076/.040/IPC-7351 (2005)/NORMAL]
R20  200k  [R/SM/0805/IPC-7351 (2005)/NORMAL]
R21  2k4  [R/SM/0805/IPC-7351 (2005)/NORMAL]
R22  2k4  [R/SM/0805/IPC-7351 (2005)/NORMAL]
R23  1K8  [R/SM/0805/IPC-7351 (2005)/NORMAL]
R24  1K8  [R/SM/0805/IPC-7351 (2005)/NORMAL]
R25  442k  [R/SM/0805/IPC-7351 (2005)/NORMAL]
R26  510R  [R/SM/0805/IPC-7351 (2005)/NORMAL]
R27  1K5  [R/SM/0805/IPC-7351 (2005)/NORMAL]
R28  3k9/0,25W  [R/SM/1206/IPC-7351 (2005)/NORMAL]
TVS2  SMAJ15A  [SM/DO214AC/IPC-7351 (2005)/NORMAL]
TVS3  SMAJ15A  [SM/DO214AC/IPC-7351 (2005)/NORMAL]
U4  LM7812ABD2T  [TO220/VER/.076/.052]
U5  LT3088  [SM/SOT223]
U6  7912ACD2T  [TO220/VER/.076/.052]
U7  LT3088  [SM/SOT223]
U8  LT3088  [SM/SOT223]
sheet B4B01
C58  100nF  [C/SM/0805/IPC-7351 (2005)/NORMAL]
C59  10uF/25V  [C/SM/1210/IPC-7351 (2005)/NORMAL]
C60  10uF/25V  [C/SM/1210/IPC-7351 (2005)/NORMAL]
C61  1nF  [C/SM/0805/IPC-7351 (2005)/NORMAL]
C62  1nF  [C/SM/0805/IPC-7351 (2005)/NORMAL]
C63  27pF  [C/SM/0805/IPC-7351 (2005)/NORMAL]
C64  1nF  [C/SM/0805/IPC-7351 (2005)/NORMAL]
C65  100nF  [C/SM/0805/IPC-7351 (2005)/NORMAL]
C66  100nF  [C/SM/0805/IPC-7351 (2005)/NORMAL]
C67  100nF  [C/SM/0805/IPC-7351 (2005)/NORMAL]
C68  100nF  [C/SM/0805/IPC-7351 (2005)/NORMAL]
C69  27pF  [C/SM/0805/IPC-7351 (2005)/NORMAL]
LED11  LH R974  [LED/SM/0805/IPC-7351 (2005)/NORMAL]
R91  2k7  [R/SM/0805/IPC-7351 (2005)/NORMAL]
R92  16k  [R/SM/0805/IPC-7351 (2005)/NORMAL]
R93  20R0/0.25W/0.1%  [R/SM/1206/IPC-7351 (2005)/NORMAL]
R94  100k/0.1%  [R/SM/0805/IPC-7351 (2005)/NORMAL]
R95  10k  [R/SM/0805/IPC-7351 (2005)/NORMAL]
R96  20R0/0.25W/0.1%  [R/SM/1206/IPC-7351 (2005)/NORMAL]
R97  10R/0.66W/5%  [R/SM/1206/IPC-7351 (2005)/NORMAL]
R98  20R0/0.25W/0.1%  [R/SM/1206/IPC-7351 (2005)/NORMAL]
R99  100k/0.1%  [R/SM/0805/IPC-7351 (2005)/NORMAL]
R100  20R0/0.25W/0.1%  [R/SM/1206/IPC-7351 (2005)/NORMAL]
R101  100k/0.1%  [R/SM/0805/IPC-7351 (2005)/NORMAL]
R102  100k/0.1%  [R/SM/0805/IPC-7351 (2005)/NORMAL]
R103  1k20/0.1%  [R/SM/0805/IPC-7351 (2005)/NORMAL]
R104  2k00/0.1%  [R/SM/0805/IPC-7351 (2005)/NORMAL]
TVS49  SMAJ8.5CA  [SM/DO214AC/IPC-7351 (2005)/NORMAL]
U25  OPA132  [SM/SOIC.050/08/WB.150/L.200/IPC-7351 (2005)/NORMAL]
U26  LMH6321  [SM/TO263/D2PAK/THV 42X.012/7/IPC-7351 (2005)/NORMAL]
U27  AD8130  [SM/SOIC.050/08/WB.150/L.200/IPC-7351 (2005)/NORMAL]
sheet B4B08
C142  100nF  [C/SM/0805/IPC-7351 (2005)/NORMAL]
C143  10uF/25V  [C/SM/1210/IPC-7351 (2005)/NORMAL]
C144  10uF/25V  [C/SM/1210/IPC-7351 (2005)/NORMAL]
C145  1nF  [C/SM/0805/IPC-7351 (2005)/NORMAL]
C146  1nF  [C/SM/0805/IPC-7351 (2005)/NORMAL]
C147  27pF  [C/SM/0805/IPC-7351 (2005)/NORMAL]
C148  1nF  [C/SM/0805/IPC-7351 (2005)/NORMAL]
C149  100nF  [C/SM/0805/IPC-7351 (2005)/NORMAL]
C150  100nF  [C/SM/0805/IPC-7351 (2005)/NORMAL]
C151  100nF  [C/SM/0805/IPC-7351 (2005)/NORMAL]
C152  27pF  [C/SM/0805/IPC-7351 (2005)/NORMAL]
C153  100nF  [C/SM/0805/IPC-7351 (2005)/NORMAL]
LED18  LH R974  [LED/SM/0805/IPC-7351 (2005)/NORMAL]
R189  2k7  [R/SM/0805/IPC-7351 (2005)/NORMAL]
R190  16K  [R/SM/0805/IPC-7351 (2005)/NORMAL]
R191  20R0/0.25W/0.1%  [R/SM/1206/IPC-7351 (2005)/NORMAL]
R192  100k/0.1%  [R/SM/0805/IPC-7351 (2005)/NORMAL]
R193  10k  [R/SM/0805/IPC-7351 (2005)/NORMAL]
R194  20R0/0.25W/0.1%  [R/SM/1206/IPC-7351 (2005)/NORMAL]
R195  10R/0.66W/5%  [R/SM/1206/IPC-7351 (2005)/NORMAL]
R196  20R0/0.25W/0.1%  [R/SM/1206/IPC-7351 (2005)/NORMAL]
R197  100k/0.1%  [R/SM/0805/IPC-7351 (2005)/NORMAL]
R198  20R0/0.25W/0.1%  [R/SM/1206/IPC-7351 (2005)/NORMAL]
R199  100k/0.1%  [R/SM/0805/IPC-7351 (2005)/NORMAL]
R200  100k/0.1%  [R/SM/0805/IPC-7351 (2005)/NORMAL]
R201  1k20/0.1%  [R/SM/0805/IPC-7351 (2005)/NORMAL]
R202  2k00/0.1%  [R/SM/0805/IPC-7351 (2005)/NORMAL]
TVS56  SMAJ8.5CA  [SM/DO214AC/IPC-7351 (2005)/NORMAL]
U46  OPA132  [SM/SOIC.050/08/WB.150/L.200/IPC-7351 (2005)/NORMAL]
U47  LMH6321  [SM/TO263/D2PAK/THV 42X.012/7/IPC-7351 (2005)/NORMAL]
U48  AD8130  [SM/SOIC.050/08/WB.150/L.200/IPC-7351 (2005)/NORMAL]
sheet B4B09
C154  100nF  [C/SM/0805/IPC-7351 (2005)/NORMAL]
C155  10uF/25V  [C/SM/1210/IPC-7351 (2005)/NORMAL]
C156  10uF/25V  [C/SM/1210/IPC-7351 (2005)/NORMAL]
C157  1nF  [C/SM/0805/IPC-7351 (2005)/NORMAL]
C158  1nF  [C/SM/0805/IPC-7351 (2005)/NORMAL]
C159  27pF  [C/SM/0805/IPC-7351 (2005)/NORMAL]
C160  1nF  [C/SM/0805/IPC-7351 (2005)/NORMAL]
C161  100nF  [C/SM/0805/IPC-7351 (2005)/NORMAL]
C162  100nF  [C/SM/0805/IPC-7351 (2005)/NORMAL]
C163  27pF  [C/SM/0805/IPC-7351 (2005)/NORMAL]
C164  100nF  [C/SM/0805/IPC-7351 (2005)/NORMAL]
C165  100nF  [C/SM/0805/IPC-7351 (2005)/NORMAL]
LED19  LH R974  [LED/SM/0805/IPC-7351 (2005)/NORMAL]
R203  2k7  [R/SM/0805/IPC-7351 (2005)/NORMAL]
R204  16k  [R/SM/0805/IPC-7351 (2005)/NORMAL]
R205  20R0/0.25W/0.1%  [R/SM/1206/IPC-7351 (2005)/NORMAL]
R206  100k/0.1%  [R/SM/0805/IPC-7351 (2005)/NORMAL]
R207  10k  [R/SM/0805/IPC-7351 (2005)/NORMAL]
R208  20R0/0.25W/0.1%  [R/SM/1206/IPC-7351 (2005)/NORMAL]
R209  10R/0.66W/5%  [R/SM/1206/IPC-7351 (2005)/NORMAL]
R210  20R0/0.25W/0.1%  [R/SM/1206/IPC-7351 (2005)/NORMAL]
R211  100k/0.1%  [R/SM/0805/IPC-7351 (2005)/NORMAL]
R212  20R0/0.25W/0.1%  [R/SM/1206/IPC-7351 (2005)/NORMAL]
R213  100k/0.1%  [R/SM/0805/IPC-7351 (2005)/NORMAL]
R214  100k/0.1%  [R/SM/0805/IPC-7351 (2005)/NORMAL]
R215  1k20/0.1%  [R/SM/0805/IPC-7351 (2005)/NORMAL]
R216  2k00/0.1%  [R/SM/0805/IPC-7351 (2005)/NORMAL]
TVS57  SMAJ8.5CA  [SM/DO214AC/IPC-7351 (2005)/NORMAL]
U49  OPA132  [SM/SOIC.050/08/WB.150/L.200/IPC-7351 (2005)/NORMAL]
U50  LMH6321  [SM/TO263/D2PAK/THV 42X.012/7/IPC-7351 (2005)/NORMAL]
U51  AD8130  [SM/SOIC.050/08/WB.150/L.200/IPC-7351 (2005)/NORMAL]
sheet B4B11
C178  100nF  [C/SM/0805/IPC-7351 (2005)/NORMAL]
C179  10uF/25V  [C/SM/1210/IPC-7351 (2005)/NORMAL]
C180  10uF/25V  [C/SM/1210/IPC-7351 (2005)/NORMAL]
C181  1nF  [C/SM/0805/IPC-7351 (2005)/NORMAL]
C182  1nF  [C/SM/0805/IPC-7351 (2005)/NORMAL]
C183  330pF  [C/SM/0805/IPC-7351 (2005)/NORMAL]
C184  1nF  [C/SM/0805/IPC-7351 (2005)/NORMAL]
C185  100nF  [C/SM/0805/IPC-7351 (2005)/NORMAL]
C186  100nF  [C/SM/0805/IPC-7351 (2005)/NORMAL]
C187  100nF  [C/SM/0805/IPC-7351 (2005)/NORMAL]
C188  100nF  [C/SM/0805/IPC-7351 (2005)/NORMAL]
C189  27pF  [C/SM/0805/IPC-7351 (2005)/NORMAL]
LED21  LH R974  [LED/SM/0805/IPC-7351 (2005)/NORMAL]
R231  2k7  [R/SM/0805/IPC-7351 (2005)/NORMAL]
R232  200k  [R/SM/0805/IPC-7351 (2005)/NORMAL]
R233  100R/0.1%  [R/SM/1206/IPC-7351 (2005)/NORMAL]
R234  100k/0.1%  [R/SM/0805/IPC-7351 (2005)/NORMAL]
R235  240R/0.1%  [R/SM/1206/IPC-7351 (2005)/NORMAL]
R236  10k  [R/SM/0805/IPC-7351 (2005)/NORMAL]
R237  150R  [R/SM/1206/IPC-7351 (2005)/NORMAL]
R238  NM  [R/SM/1206/IPC-7351 (2005)/NORMAL]
R239  100k/0.1%  [R/SM/0805/IPC-7351 (2005)/NORMAL]
R240  NM  [R/SM/1206/IPC-7351 (2005)/NORMAL]
R241  100k/0.1%  [R/SM/0805/IPC-7351 (2005)/NORMAL]
R242  100k/0.1%  [R/SM/0805/IPC-7351 (2005)/NORMAL]
R243  1k20/0.1%  [R/SM/0805/IPC-7351 (2005)/NORMAL]
R244  2k00/0.1%  [R/SM/0805/IPC-7351 (2005)/NORMAL]
TVS59  SMAJ8.5CA  [SM/DO214AC/IPC-7351 (2005)/NORMAL]
U55  OPA132  [SM/SOIC.050/08/WB.150/L.200/IPC-7351 (2005)/NORMAL]
U56  LMH6321  [SM/TO263/D2PAK/THV 42X.012/7/IPC-7351 (2005)/NORMAL]
U57  AD8130  [SM/SOIC.050/08/WB.150/L.200/IPC-7351 (2005)/NORMAL]
sheet B4B12
C190  100nF  [C/SM/0805/IPC-7351 (2005)/NORMAL]
C191  10uF/25V  [C/SM/1210/IPC-7351 (2005)/NORMAL]
C192  10uF/25V  [C/SM/1210/IPC-7351 (2005)/NORMAL]
C193  1nF  [C/SM/0805/IPC-7351 (2005)/NORMAL]
C194  1nF  [C/SM/0805/IPC-7351 (2005)/NORMAL]
C195  330pF  [C/SM/0805/IPC-7351 (2005)/NORMAL]
C196  1nF  [C/SM/0805/IPC-7351 (2005)/NORMAL]
C197  100nF  [C/SM/0805/IPC-7351 (2005)/NORMAL]
C198  100nF  [C/SM/0805/IPC-7351 (2005)/NORMAL]
C199  27pF  [C/SM/0805/IPC-7351 (2005)/NORMAL]
C200  100nF  [C/SM/0805/IPC-7351 (2005)/NORMAL]
C201  100nF  [C/SM/0805/IPC-7351 (2005)/NORMAL]
LED22  LH R974  [LED/SM/0805/IPC-7351 (2005)/NORMAL]
R245  2k7  [R/SM/0805/IPC-7351 (2005)/NORMAL]
R246  200k  [R/SM/0805/IPC-7351 (2005)/NORMAL]
R247  100R/0.1%  [R/SM/1206/IPC-7351 (2005)/NORMAL]
R248  100k/0.1%  [R/SM/0805/IPC-7351 (2005)/NORMAL]
R249  240R/0,1%  [R/SM/1206/IPC-7351 (2005)/NORMAL]
R250  10k  [R/SM/0805/IPC-7351 (2005)/NORMAL]
R251  150R  [R/SM/1206/IPC-7351 (2005)/NORMAL]
R252  NM  [R/SM/1206/IPC-7351 (2005)/NORMAL]
R253  100k/0.1%  [R/SM/0805/IPC-7351 (2005)/NORMAL]
R254  NM  [R/SM/1206/IPC-7351 (2005)/NORMAL]
R255  100k/0.1%  [R/SM/0805/IPC-7351 (2005)/NORMAL]
R256  100k/0.1%  [R/SM/0805/IPC-7351 (2005)/NORMAL]
R257  1k20/0.1%  [R/SM/0805/IPC-7351 (2005)/NORMAL]
R258  2k00/0.1%  [R/SM/0805/IPC-7351 (2005)/NORMAL]
TVS60  SMAJ8.5CA  [SM/DO214AC/IPC-7351 (2005)/NORMAL]
U58  OPA132  [SM/SOIC.050/08/WB.150/L.200/IPC-7351 (2005)/NORMAL]
U59  LMH6321  [SM/TO263/D2PAK/THV 42X.012/7/IPC-7351 (2005)/NORMAL]
U60  AD8130  [SM/SOIC.050/08/WB.150/L.200/IPC-7351 (2005)/NORMAL]
sheet B4B13
C202  100nF  [C/SM/0805/IPC-7351 (2005)/NORMAL]
C203  10uF/25V  [C/SM/1210/IPC-7351 (2005)/NORMAL]
C204  10uF/25V  [C/SM/1210/IPC-7351 (2005)/NORMAL]
C205  1nF  [C/SM/0805/IPC-7351 (2005)/NORMAL]
C206  1nF  [C/SM/0805/IPC-7351 (2005)/NORMAL]
C207  330pF  [C/SM/0805/IPC-7351 (2005)/NORMAL]
C208  1nF  [C/SM/0805/IPC-7351 (2005)/NORMAL]
C209  100nF  [C/SM/0805/IPC-7351 (2005)/NORMAL]
C210  100nF  [C/SM/0805/IPC-7351 (2005)/NORMAL]
C211  27pF  [C/SM/0805/IPC-7351 (2005)/NORMAL]
C212  100nF  [C/SM/0805/IPC-7351 (2005)/NORMAL]
C213  100nF  [C/SM/0805/IPC-7351 (2005)/NORMAL]
LED23  LH R974  [LED/SM/0805/IPC-7351 (2005)/NORMAL]
R259  2k7  [R/SM/0805/IPC-7351 (2005)/NORMAL]
R260  200k  [R/SM/0805/IPC-7351 (2005)/NORMAL]
R261  100R/0.1%  [R/SM/1206/IPC-7351 (2005)/NORMAL]
R262  100k/0.1%  [R/SM/0805/IPC-7351 (2005)/NORMAL]
R263  10k  [R/SM/0805/IPC-7351 (2005)/NORMAL]
R264  240R/0,1%  [R/SM/1206/IPC-7351 (2005)/NORMAL]
R265  150R  [R/SM/1206/IPC-7351 (2005)/NORMAL]
R266  NM  [R/SM/1206/IPC-7351 (2005)/NORMAL]
R267  100k/0.1%  [R/SM/0805/IPC-7351 (2005)/NORMAL]
R268  NM  [R/SM/1206/IPC-7351 (2005)/NORMAL]
R269  100k/0.1%  [R/SM/0805/IPC-7351 (2005)/NORMAL]
R270  100k/0.1%  [R/SM/0805/IPC-7351 (2005)/NORMAL]
R271  1k20/0.1%  [R/SM/0805/IPC-7351 (2005)/NORMAL]
R272  2k00/0.1%  [R/SM/0805/IPC-7351 (2005)/NORMAL]
TVS61  SMAJ8.5CA  [SM/DO214AC/IPC-7351 (2005)/NORMAL]
U61  OPA132  [SM/SOIC.050/08/WB.150/L.200/IPC-7351 (2005)/NORMAL]
U62  LMH6321  [SM/TO263/D2PAK/THV 42X.012/7/IPC-7351 (2005)/NORMAL]
U63  AD8130  [SM/SOIC.050/08/WB.150/L.200/IPC-7351 (2005)/NORMAL]
sheet B4B14
C214  100nF  [C/SM/0805/IPC-7351 (2005)/NORMAL]
C215  10uF/25V  [C/SM/1210/IPC-7351 (2005)/NORMAL]
C216  10uF/25V  [C/SM/1210/IPC-7351 (2005)/NORMAL]
C217  1nF  [C/SM/0805/IPC-7351 (2005)/NORMAL]
C218  1nF  [C/SM/0805/IPC-7351 (2005)/NORMAL]
C219  820pF  [C/SM/0805/IPC-7351 (2005)/NORMAL]
C220  1nF  [C/SM/0805/IPC-7351 (2005)/NORMAL]
C221  100nF  [C/SM/0805/IPC-7351 (2005)/NORMAL]
C222  100nF  [C/SM/0805/IPC-7351 (2005)/NORMAL]
C223  27pF  [C/SM/0805/IPC-7351 (2005)/NORMAL]
C224  100nF  [C/SM/0805/IPC-7351 (2005)/NORMAL]
C225  100nF  [C/SM/0805/IPC-7351 (2005)/NORMAL]
LED24  LH R974  [LED/SM/0805/IPC-7351 (2005)/NORMAL]
R273  2k7  [R/SM/0805/IPC-7351 (2005)/NORMAL]
R274  75k  [R/SM/0805/IPC-7351 (2005)/NORMAL]
R275  100R/0.1%  [R/SM/1206/IPC-7351 (2005)/NORMAL]
R276  100k/0.1%  [R/SM/0805/IPC-7351 (2005)/NORMAL]
R277  100R/0.1%  [R/SM/1206/IPC-7351 (2005)/NORMAL]
R278  10k  [R/SM/0805/IPC-7351 (2005)/NORMAL]
R279  47R/0.25W/5%  [R/SM/1206/IPC-7351 (2005)/NORMAL]
R280  100R/0.1%  [R/SM/1206/IPC-7351 (2005)/NORMAL]
R281  100k/0.1%  [R/SM/0805/IPC-7351 (2005)/NORMAL]
R282  100R/0.1%  [R/SM/1206/IPC-7351 (2005)/NORMAL]
R283  100k/0.1%  [R/SM/0805/IPC-7351 (2005)/NORMAL]
R284  100k/0.1%  [R/SM/0805/IPC-7351 (2005)/NORMAL]
R285  1k20/0.1%  [R/SM/0805/IPC-7351 (2005)/NORMAL]
R286  2k00/0.1%  [R/SM/0805/IPC-7351 (2005)/NORMAL]
TVS62  SMAJ8.5CA  [SM/DO214AC/IPC-7351 (2005)/NORMAL]
U64  OPA132  [SM/SOIC.050/08/WB.150/L.200/IPC-7351 (2005)/NORMAL]
U65  LMH6321  [SM/TO263/D2PAK/THV 42X.012/7/IPC-7351 (2005)/NORMAL]
U66  AD8130  [SM/SOIC.050/08/WB.150/L.200/IPC-7351 (2005)/NORMAL]
sheet B4B15
C226  100nF  [C/SM/0805/IPC-7351 (2005)/NORMAL]
C227  10uF/25V  [C/SM/1210/IPC-7351 (2005)/NORMAL]
C228  10uF/25V  [C/SM/1210/IPC-7351 (2005)/NORMAL]
C229  1nF  [C/SM/0805/IPC-7351 (2005)/NORMAL]
C230  1nF  [C/SM/0805/IPC-7351 (2005)/NORMAL]
C231  820pF  [C/SM/0805/IPC-7351 (2005)/NORMAL]
C232  1nF  [C/SM/0805/IPC-7351 (2005)/NORMAL]
C233  100nF  [C/SM/0805/IPC-7351 (2005)/NORMAL]
C234  100nF  [C/SM/0805/IPC-7351 (2005)/NORMAL]
C235  100nF  [C/SM/0805/IPC-7351 (2005)/NORMAL]
C236  100nF  [C/SM/0805/IPC-7351 (2005)/NORMAL]
C237  27pF  [C/SM/0805/IPC-7351 (2005)/NORMAL]
LED25  LH R974  [LED/SM/0805/IPC-7351 (2005)/NORMAL]
R287  2k7  [R/SM/0805/IPC-7351 (2005)/NORMAL]
R288  75K  [R/SM/0805/IPC-7351 (2005)/NORMAL]
R289  100R/0.1%  [R/SM/1206/IPC-7351 (2005)/NORMAL]
R290  100k/0.1%  [R/SM/0805/IPC-7351 (2005)/NORMAL]
R291  100R/0.1%  [R/SM/1206/IPC-7351 (2005)/NORMAL]
R292  10k  [R/SM/0805/IPC-7351 (2005)/NORMAL]
R293  47R/0.25W/5%  [R/SM/1206/IPC-7351 (2005)/NORMAL]
R294  100R/0.1%  [R/SM/1206/IPC-7351 (2005)/NORMAL]
R295  100k/0.1%  [R/SM/0805/IPC-7351 (2005)/NORMAL]
R296  100R/0.1%  [R/SM/1206/IPC-7351 (2005)/NORMAL]
R297  100k/0.1%  [R/SM/0805/IPC-7351 (2005)/NORMAL]
R298  100k/0.1%  [R/SM/0805/IPC-7351 (2005)/NORMAL]
R299  1k20/0.1%  [R/SM/0805/IPC-7351 (2005)/NORMAL]
R300  2k00/0.1%  [R/SM/0805/IPC-7351 (2005)/NORMAL]
TVS63  SMAJ8.5CA  [SM/DO214AC/IPC-7351 (2005)/NORMAL]
U67  OPA132  [SM/SOIC.050/08/WB.150/L.200/IPC-7351 (2005)/NORMAL]
U68  LMH6321  [SM/TO263/D2PAK/THV 42X.012/7/IPC-7351 (2005)/NORMAL]
U69  AD8130  [SM/SOIC.050/08/WB.150/L.200/IPC-7351 (2005)/NORMAL]
sheet B4B16
C238  100nF  [C/SM/0805/IPC-7351 (2005)/NORMAL]
C239  10uF/25V  [C/SM/1210/IPC-7351 (2005)/NORMAL]
C240  10uF/25V  [C/SM/1210/IPC-7351 (2005)/NORMAL]
C241  1nF  [C/SM/0805/IPC-7351 (2005)/NORMAL]
C242  1nF  [C/SM/0805/IPC-7351 (2005)/NORMAL]
C243  820pF  [C/SM/0805/IPC-7351 (2005)/NORMAL]
C244  1nF  [C/SM/0805/IPC-7351 (2005)/NORMAL]
C245  100nF  [C/SM/0805/IPC-7351 (2005)/NORMAL]
C246  100nF  [C/SM/0805/IPC-7351 (2005)/NORMAL]
C247  100nF  [C/SM/0805/IPC-7351 (2005)/NORMAL]
C248  100nF  [C/SM/0805/IPC-7351 (2005)/NORMAL]
C249  27pF  [C/SM/0805/IPC-7351 (2005)/NORMAL]
LED26  LH R974  [LED/SM/0805/IPC-7351 (2005)/NORMAL]
R301  2k7  [R/SM/0805/IPC-7351 (2005)/NORMAL]
R302  75k  [R/SM/0805/IPC-7351 (2005)/NORMAL]
R303  100R/0.1%  [R/SM/1206/IPC-7351 (2005)/NORMAL]
R304  100k/0.1%  [R/SM/0805/IPC-7351 (2005)/NORMAL]
R305  100R/0.1%  [R/SM/1206/IPC-7351 (2005)/NORMAL]
R306  10k  [R/SM/0805/IPC-7351 (2005)/NORMAL]
R307  47R/0.25W/5%  [R/SM/1206/IPC-7351 (2005)/NORMAL]
R308  100R/0.1%  [R/SM/1206/IPC-7351 (2005)/NORMAL]
R309  100k/0.1%  [R/SM/0805/IPC-7351 (2005)/NORMAL]
R310  100R/0.1%  [R/SM/1206/IPC-7351 (2005)/NORMAL]
R311  100k/0.1%  [R/SM/0805/IPC-7351 (2005)/NORMAL]
R312  100k/0.1%  [R/SM/0805/IPC-7351 (2005)/NORMAL]
R313  1k20/0.1%  [R/SM/0805/IPC-7351 (2005)/NORMAL]
R314  2k00/0.1%  [R/SM/0805/IPC-7351 (2005)/NORMAL]
TVS64  SMAJ8.5CA  [SM/DO214AC/IPC-7351 (2005)/NORMAL]
U70  OPA132  [SM/SOIC.050/08/WB.150/L.200/IPC-7351 (2005)/NORMAL]
U71  LMH6321  [SM/TO263/D2PAK/THV 42X.012/7/IPC-7351 (2005)/NORMAL]
U72  AD8130  [SM/SOIC.050/08/WB.150/L.200/IPC-7351 (2005)/NORMAL]
sheet B4B21
C262  100nF  [C/SM/0805/IPC-7351 (2005)/NORMAL]
C263  10uF/10V  [SM/A-1206/IPC-7351 (2005)/NORMAL]
C264  100nF  [C/SM/0805/IPC-7351 (2005)/NORMAL]
C265  10uF/10V  [SM/A-1206/IPC-7351 (2005)/NORMAL]
C266  100nF  [C/SM/0805/IPC-7351 (2005)/NORMAL]
C267  10uF/10V  [SM/A-1206/IPC-7351 (2005)/NORMAL]
C268  100nF  [C/SM/0805/IPC-7351 (2005)/NORMAL]
C269  10uF/10V  [SM/A-1206/IPC-7351 (2005)/NORMAL]
C270  100nF  [C/SM/0805/IPC-7351 (2005)/NORMAL]
C271  10uF/10V  [SM/A-1206/IPC-7351 (2005)/NORMAL]
C272  100nF  [C/SM/0805/IPC-7351 (2005)/NORMAL]
C273  10uF/10V  [SM/A-1206/IPC-7351 (2005)/NORMAL]
C274  100nF  [C/SM/0805/IPC-7351 (2005)/NORMAL]
C275  10uF/10V  [SM/A-1206/IPC-7351 (2005)/NORMAL]
C276  100nF  [C/SM/0805/IPC-7351 (2005)/NORMAL]
C277  10uF/10V  [SM/A-1206/IPC-7351 (2005)/NORMAL]
C278  100nF  [C/SM/0805/IPC-7351 (2005)/NORMAL]
C279  10uF/10V  [SM/A-1206/IPC-7351 (2005)/NORMAL]
C280  100nF  [C/SM/0805/IPC-7351 (2005)/NORMAL]
C281  10uF/10V  [SM/A-1206/IPC-7351 (2005)/NORMAL]
C282  100nF  [C/SM/0805/IPC-7351 (2005)/NORMAL]
C283  10uF/10V  [SM/A-1206/IPC-7351 (2005)/NORMAL]
C284  100nF  [C/SM/0805/IPC-7351 (2005)/NORMAL]
C285  10uF/10V  [SM/A-1206/IPC-7351 (2005)/NORMAL]
C286  100nF  [C/SM/0805/IPC-7351 (2005)/NORMAL]
C287  10uF/10V  [SM/A-1206/IPC-7351 (2005)/NORMAL]
C288  100nF  [C/SM/0805/IPC-7351 (2005)/NORMAL]
C289  10uF/10V  [SM/A-1206/IPC-7351 (2005)/NORMAL]
C290  100nF  [C/SM/0805/IPC-7351 (2005)/NORMAL]
C291  10uF/10V  [SM/A-1206/IPC-7351 (2005)/NORMAL]
C292  100nF  [C/SM/0805/IPC-7351 (2005)/NORMAL]
C293  10uF/10V  [SM/A-1206/IPC-7351 (2005)/NORMAL]
C294  100nF  [C/SM/0805/IPC-7351 (2005)/NORMAL]
C295  10uF/10V  [SM/A-1206/IPC-7351 (2005)/NORMAL]
U77  DAC121S101  [SM/SOT23/6/IPC-7351 (2005)/NORMAL]
U78  DAC121S101  [SM/SOT23/6/IPC-7351 (2005)/NORMAL]
U79  DAC121S101  [SM/SOT23/6/IPC-7351 (2005)/NORMAL]
U80  DAC121S101  [SM/SOT23/6/IPC-7351 (2005)/NORMAL]
U81  DAC121S101  [SM/SOT23/6/IPC-7351 (2005)/NORMAL]
U82  DAC121S101  [SM/SOT23/6/IPC-7351 (2005)/NORMAL]
U83  DAC121S101  [SM/SOT23/6/IPC-7351 (2005)/NORMAL]
U84  DAC121S101  [SM/SOT23/6/IPC-7351 (2005)/NORMAL]
U85  DAC121S101  [SM/SOT23/6/IPC-7351 (2005)/NORMAL]
U86  DAC121S101  [SM/SOT23/6/IPC-7351 (2005)/NORMAL]
U87  DAC121S101  [SM/SOT23/6/IPC-7351 (2005)/NORMAL]
U88  DAC121S101  [SM/SOT23/6/IPC-7351 (2005)/NORMAL]
U89  DAC121S101  [SM/SOT23/6/IPC-7351 (2005)/NORMAL]
U90  DAC121S101  [SM/SOT23/6/IPC-7351 (2005)/NORMAL]
U91  DAC121S101  [SM/SOT23/6/IPC-7351 (2005)/NORMAL]
U92  DAC121S101  [SM/SOT23/6/IPC-7351 (2005)/NORMAL]
U93  DAC121S101  [SM/SOT23/6/IPC-7351 (2005)/NORMAL]

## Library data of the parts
+5VA +10VA +12VA +15VA +22VA -12VA -15VA = TEST_POINT
C13-C15 C20-C22 C25 = CAP_NP: RS: 723-6584
C16 C23 C26 C59 C60 C143 C144 C155 C156 C179 C180 C191 C192 C203 C204 C215 C216 C227 C228 C239 C240 = CAP_NP: RS: 790-0632
C17 C19 = CAP_POL: RS: 684-1762
C18 C24 C27 = CAP_NP: RS: 723-6401
D3-D6 = DIODE: RS: 670-8817
FIL1 FIL2 = BNX002-01: RS: 209-077
L3-L5 = CHOKE_IRON: RS: 724-1598
LED4-LED10 = LED: RS: 654-5773
R17 R19 = R_PTC_(V): RS: 517-6736
R18 R94 R99 R101 R102 R192 R197 R199 R200 R206 R211 R213 R214 R234 R239 R241 R242 R248 R253 R255 R256 R262 R267 R269 R270 R276 R281 R283 R284 R290 R295 R297 R298 R304 R309 R311 R312 = R: RS: 566-765
R20 = R: RS: 828-0594
R21-R24 R26 R27 R91 R92 R95 R189 R190 R193 R203 R204 R207 R231 R232 R235 R236 R238 R240 R245 R246 R249 R250 R252 R254 R259 R260 R263 R264 R266 R268 R273 R274 R278 R287 R288 R292 R301 R302 R306 = R
R25 = R: RS: 708-6922
R28 = R: RS: 223-2344
TVS2 TVS3 = DIODE_ZENER_1: RS: 764-5537
U4 = LM78xx: RS: 785-6958
U5 U7 = LT3088_3: Farnell: 2483269
U6 = LM79xx: RS: 774-3552
U8 = LT3088_2: Farnell: 2483269
C58 C65-C68 C142 C149-C151 C153 C154 C161 C162 C164 C165 C178 C185-C188 C190 C197 C198 C200-C202 C209 C210 C212-C214 C221 C222 C224-C226 C233-C236 C238 C245-C248 C262 C264 C266 C268 C270 C272 C274 C276 C278 C280 C282 C284 C286 C288 C290 C292 C294 = CAP_NP: RS: 723-5058
C61 C62 C64 C145 C146 C148 C157 C158 C160 C181 C182 C184 C193 C194 C196 C205 C206 C208 C217 C218 C220 C229 C230 C232 C241 C242 C244 = CAP_NP: RS: 723-6196
C63 C69 C147 C152 C159 C163 C189 C199 C211 C223 C237 C249 = CAP_NP: Farnell: 1414683
LED11 LED18 LED19 LED21-LED26 = LED: RS: 654-5818
R93 R96 R98 R100 R191 R194 R196 R198 R205 R208 R210 R212 = R: Farnell: 1501421
R97 R195 R209 = R: RS: 153-696
R103 R201 R215 R243 R257 R271 R285 R299 R313 = R: RS: 565-926
R104 R202 R216 R244 R258 R272 R286 R300 R314 = R: RS: 828-0554
TVS49 TVS56 TVS57 TVS59-TVS64 = TVS-BIDIRECTIONAL
U25 U46 U49 U55 U58 U61 U64 U67 U70 = OPA132_(SOIC8): MFR. P/N: OPA132UA; RS: 218-8275
U26 U47 U50 U56 U59 U62 U65 U68 U71 = LMH6321_(TO263)_0: MFR. P/N: LMH6321TS/NOPB; RS: 655-3831
U27 U48 U51 U57 U60 U63 U66 U69 U72 = AD8130_(SOIC8): MFR. P/N: AD8130ARZ; RS: 497-2268
C183 C195 C207 = CAP_NP: Farnell: 1414686
R233 R247 R261 R275 R277 R280 R282 R289 R291 R294 R296 R303 R305 R308 R310 = R: RS: 669-6503
R237 R251 R265 = R: RS: 721-9765
C219 C231 C243 = CAP_NP: Farnell: 2409058
R279 R293 R307 = R: RS: 721-8823
C263 C265 C267 C269 C271 C273 C275 C277 C279 C281 C283 C285 C287 C289 C291 C293 C295 = CAP_POL: MFR. P/N: T491A106M010AT; RS: 144-7491
U77-U93 = DAC121S101: Farnell: 1101198

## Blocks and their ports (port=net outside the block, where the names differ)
Alimentacion/Alimentacion Analogica = schematic B1B2 Alimentacion Analogica, on sheet B1: no ports
Alimentacion/Alimentacion Digital = schematic B1B1 Alimentacion Digital, on sheet B1: VCCIO_EN=N08147, PG_CARRIER=N08032

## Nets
+5VA: +5VA.1 C16.1 R26.2 U5.2(OUT) U5.4(OUT) U77.3(VA) U78.3(VA) U79.3(VA) U80.3(VA) U81.3(VA) U82.3(VA) U83.3(VA) U84.3(VA) U85.3(VA) U86.3(VA) U87.3(VA) U88.3(VA) U89.3(VA) U90.3(VA) U91.3(VA) U92.3(VA) U93.3(VA) ; also on sheet 2 4 5 7
+10VA: +10VA.1 C23.1 R27.2 U7.2(OUT) U7.4(OUT)
+12VA: +12VA.1 C14.1 D3.2(ANODE) D4.1(CATHODE) R23.2 R92.2 R190.2 R204.2 R232.2 R246.2 R260.2 R274.2 R288.2 R302.2 U4.3(OUT) U27.3(/PD) U27.7(+Vs) U48.3(/PD) U48.7(+Vs) U51.3(/PD) U51.7(+Vs) U57.3(/PD) U57.7(+Vs) U60.3(/PD) U60.7(+Vs) U63.3(/PD) U63.7(+Vs) U66.3(/PD) U66.7(+Vs) U69.3(/PD) U69.7(+Vs) U72.3(/PD) U72.7(+Vs) ; also on sheet 3 6 8 9 10 11 12
+15VA: +15VA.1 C13.1 C58.2 C59.1 C142.2 C143.1 C154.2 C155.1 C178.2 C179.1 C190.2 C191.1 C202.2 C203.1 C214.2 C215.1 C226.2 C227.1 C238.2 C239.1 D3.1(CATHODE) FIL1.6(CB) L3.2 LED11.2(ANODE) LED18.2(ANODE) LED19.2(ANODE) LED21.2(ANODE) LED22.2(ANODE) LED23.2(ANODE) LED24.2(ANODE) LED25.2(ANODE) LED26.2(ANODE) R21.2 U4.1(IN) U25.7(+Vs) U26.5(+Vs) U46.7(+Vs) U47.5(+Vs) U49.7(+Vs) U50.5(+Vs) U55.7(+Vs) U56.5(+Vs) U58.7(+Vs) U59.5(+Vs) U61.7(+Vs) U62.5(+Vs) U64.7(+Vs) U65.5(+Vs) U67.7(+Vs) U68.5(+Vs) U70.7(+Vs) U71.5(+Vs) ; also on sheet 3 6 8 9 10 11 12
+15VP: R17.1
+22VA: +22VA.1 C26.1 R28.2 U8.2(OUT) U8.4(OUT) ; also on sheet 2 4 5 7
+24V: L4.2 L5.2 ; also on sheet 25 27 28 29 30
-12VA: -12VA.1 C21.2 D5.2(ANODE) D6.1(CATHODE) R24.2 U6.3(OUT) U27.2(-Vs) U48.2(-Vs) U51.2(-Vs) U57.2(-Vs) U60.2(-Vs) U63.2(-Vs) U66.2(-Vs) U69.2(-Vs) U72.2(-Vs) ; also on sheet 3 6 8 9 10 11 12
-15VA: -15VA.1 C20.2 C58.1 C60.1 C142.1 C144.1 C154.1 C156.1 C178.1 C180.1 C190.1 C192.1 C202.1 C204.1 C214.1 C216.1 C226.1 C228.1 C238.1 C240.1 D6.2(ANODE) FIL2.6(CB) R22.2 U6.2(IN) U25.4(-Vs) U26.4(-Vs) U46.4(-Vs) U47.4(-Vs) U49.4(-Vs) U50.4(-Vs) U55.4(-Vs) U56.4(-Vs) U58.4(-Vs) U59.4(-Vs) U61.4(-Vs) U62.4(-Vs) U64.4(-Vs) U65.4(-Vs) U67.4(-Vs) U68.4(-Vs) U70.4(-Vs) U71.4(-Vs) ; also on sheet 3 6 8 9 10 11 12
-15VP: R19.2
GND_ANALOG: C13.2 C14.2 C15.2 C16.2 C18.2 C20.1 C21.1 C22.2 C23.2 C24.2 C25.2 C26.2 C27.2 C59.2 C60.2 C61.1 C62.1 C63.2 C65.1 C66.1 C67.1 C68.1 C69.1 C143.2 C144.2 C145.1 C146.1 C147.2 C149.1 C150.1 C151.1 C152.1 C153.1 C155.2 C156.2 C157.1 C158.1 C159.2 C161.1 C162.1 C163.1 C164.1 C165.1 C179.2 C180.2 C181.1 C182.1 C183.2 C185.1 C186.1 C187.1 C188.1 C189.1 C191.2 C192.2 C193.1 C194.1 C195.2 C197.1 C198.1 C199.1 C200.1 C201.1 C203.2 C204.2 C205.1 C206.1 C207.2 C209.1 C210.1 C211.1 C212.1 C213.1 C215.2 C216.2 C217.1 C218.1 C219.2 C221.1 C222.1 C223.1 C224.1 C225.1 C227.2 C228.2 C229.1 C230.1 C231.2 C233.1 C234.1 C235.1 C236.1 C237.1 C239.2 C240.2 C241.1 C242.1 C243.2 C245.1 C246.1 C247.1 C248.1 C249.1 C262.1 C263.2 C264.1 C265.2 C266.1 C267.2 C268.1 C269.2 C270.1 C271.2 C272.1 C273.2 C274.1 C275.2 C276.1 C277.2 C278.1 C279.2 C280.1 C281.2 C282.1 C283.2 C284.1 C285.2 C286.1 C287.2 C288.1 C289.2 C290.1 C291.2 C292.1 C293.2 C294.1 C295.2 D4.2(ANODE) D5.1(CATHODE) FIL1.3(CG) FIL1.4(CG) FIL1.5(CG) FIL2.3(CG) FIL2.4(CG) FIL2.5(CG) LED4.1(CATHODE) LED5.2(ANODE) LED6.1(CATHODE) LED7.2(ANODE) LED8.1(CATHODE) LED9.1(CATHODE) LED10.1(CATHODE) R18.2 R20.2 R25.2 R99.1 R104.2 R197.1 R202.2 R211.1 R216.2 R239.1 R244.2 R253.1 R258.2 R267.1 R272.2 R281.1 R286.2 R295.1 R300.2 R309.1 R314.2 TVS49.2 TVS56.2 TVS57.2 TVS59.2 TVS60.2 TVS61.2 TVS62.2 TVS63.2 TVS64.2 U4.2(GND) U6.1(GND) U26.2(GND) U27.4(REF) U47.2(GND) U48.4(REF) U50.2(GND) U51.4(REF) U56.2(GND) U57.4(REF) U59.2(GND) U60.4(REF) U62.2(GND) U63.4(REF) U65.2(GND) U66.4(REF) U68.2(GND) U69.4(REF) U71.2(GND) U72.4(REF) U77.2(GND) U78.2(GND) U79.2(GND) U80.2(GND) U81.2(GND) U82.2(GND) U83.2(GND) U84.2(GND) U85.2(GND) U86.2(GND) U87.2(GND) U88.2(GND) U89.2(GND) U90.2(GND) U91.2(GND) U92.2(GND) U93.2(GND) ; also on sheet 2 3 4 5 6 7 8 9 10 11 12 25 26 31 32 33 34 35 36 37 38
GND_P: C17.2 C19.1 FIL1.1(PSG) FIL2.1(PSG) TVS2.2(ANODE) TVS3.1(CATHODE)
VCC_CIRCLE: C61.2 C62.2 C65.2 C66.2 C67.2 C68.2 C145.2 C146.2 C149.2 C150.2 C151.2 C153.2 C157.2 C158.2 C161.2 C162.2 C164.2 C165.2 C181.2 C182.2 C185.2 C186.2 C187.2 C188.2 C193.2 C194.2 C197.2 C198.2 C200.2 C201.2 C205.2 C206.2 C209.2 C210.2 C212.2 C213.2 C217.2 C218.2 C221.2 C222.2 C224.2 C225.2 C229.2 C230.2 C233.2 C234.2 C235.2 C236.2 C241.2 C242.2 C245.2 C246.2 C247.2 C248.2 C262.2 C263.1 C264.2 C265.1 C266.2 C267.1 C268.2 C269.1 C270.2 C271.1 C272.2 C273.1 C274.2 C275.1 C276.2 C277.1 C278.2 C279.1 C280.2 C281.1 C282.2 C283.1 C284.2 C285.1 C286.2 C287.1 C288.2 C289.1 C290.2 C291.1 C292.2 C293.1 C294.2 C295.1 ; also on sheet 2 3 4 5 6 7 8 9 10 11 12 27 28 29 30
Vin: R94.1 R192.1 R206.1 R234.1 R248.1 R262.1 R276.1 R290.1 R304.1 ; also on sheet 3 6 8 9 10 11 12
DAC_D0: U77.4(DIN) ; also on sheet 26
DAC_D1: U82.4(DIN) ; also on sheet 26
DAC_D2: U87.4(DIN) ; also on sheet 26
DAC_D3: U78.4(DIN) ; also on sheet 26
DAC_D4: U83.4(DIN) ; also on sheet 26
DAC_D5: U88.4(DIN) ; also on sheet 26
DAC_D6: U92.4(DIN) ; also on sheet 26
DAC_D7: U79.4(DIN) ; also on sheet 26
DAC_D8: U84.4(DIN) ; also on sheet 26
DAC_D9: U89.4(DIN) ; also on sheet 26
DAC_D10: U80.4(DIN) ; also on sheet 26
DAC_D11: U85.4(DIN) ; also on sheet 26
DAC_D12: U90.4(DIN) ; also on sheet 26
DAC_D13: U81.4(DIN) ; also on sheet 26
DAC_D14: U86.4(DIN) ; also on sheet 26
DAC_D15: U91.4(DIN) ; also on sheet 26
DAC_D16: U93.4(DIN) ; also on sheet 26
DAC_SCLK0: U79.5(SCLK) U84.5(SCLK) U92.5(SCLK) ; also on sheet 26
DAC_SCLK1: U80.5(SCLK) U88.5(SCLK) U89.5(SCLK) ; also on sheet 26
DAC_SCLK2: U78.5(SCLK) U83.5(SCLK) U85.5(SCLK) ; also on sheet 26
DAC_SCLK3: U81.5(SCLK) U87.5(SCLK) U90.5(SCLK) ; also on sheet 26
DAC_SCLK4: U77.5(SCLK) U91.5(SCLK) U93.5(SCLK) ; also on sheet 26
DAC_SCLK5: U82.5(SCLK) U86.5(SCLK) ; also on sheet 26
DAC_SYNC: U77.6(/SYNC) U78.6(/SYNC) U79.6(/SYNC) U80.6(/SYNC) U81.6(/SYNC) U82.6(/SYNC) U83.6(/SYNC) U84.6(/SYNC) U85.6(/SYNC) U86.6(/SYNC) U87.6(/SYNC) U88.6(/SYNC) U89.6(/SYNC) U90.6(/SYNC) U91.6(/SYNC) U92.6(/SYNC) U93.6(/SYNC)
DAC_V0: U77.1(Vout)
DAC_V1: U82.1(Vout)
DAC_V2: U87.1(Vout)
DAC_V3: U78.1(Vout)
DAC_V4: U83.1(Vout)
DAC_V5: U88.1(Vout)
DAC_V6: U92.1(Vout)
DAC_V7: U79.1(Vout)
DAC_V8: U84.1(Vout)
DAC_V9: U89.1(Vout)
DAC_V10: U80.1(Vout)
DAC_V11: U85.1(Vout)
DAC_V12: U90.1(Vout)
DAC_V13: U81.1(Vout)
DAC_V14: U86.1(Vout)
DAC_V15: U91.1(Vout)
M: R97.2 R195.2 R209.2 R237.2 R251.2 R265.2 R279.2 R293.2 R307.2 TVS49.1 TVS56.1 TVS57.1 TVS59.1 TVS60.1 TVS61.1 TVS62.1 TVS63.1 TVS64.1 ; also on sheet 3 6 8 9 10 11 12
VREF/2: R101.2 R200.2 R213.2 R241.2 R255.2 R269.2 R283.2 R297.2 R311.2 U93.1(Vout) ; also on sheet 3 6 8 9 10 11 12
Alimentacion/Alimentacion Analogica/N25643: C18.1 R18.1 U5.1(SET)
Alimentacion/Alimentacion Analogica/N25737: C15.1 L3.1 U5.3(VIN)
Alimentacion/Alimentacion Analogica/N26096: C24.1 R20.1 U7.1(SET)
Alimentacion/Alimentacion Analogica/N26198: C22.1 L4.1 U7.3(VIN)
Alimentacion/Alimentacion Analogica/N37766: C17.1 FIL1.2(B) R17.2 TVS2.1(CATHODE)
Alimentacion/Alimentacion Analogica/N37768: C19.2 FIL2.2(B) R19.1 TVS3.2(ANODE)
Alimentacion/Alimentacion Analogica/N38664: C27.1 R25.1 U8.1(SET)
Alimentacion/Alimentacion Analogica/N38758: C25.1 L5.1 U8.3(VIN)
N54348: LED9.2(ANODE) R27.1
N54349: LED4.2(ANODE) R21.1
N54350: LED5.1(CATHODE) R22.1
N54351: LED7.1(CATHODE) R24.1
N54352: LED10.2(ANODE) R28.1
N54355: LED6.2(ANODE) R23.1
N54356: LED8.2(ANODE) R26.1

Not connected (* = marked no-connect by the designer): C63 1; C64 1 2; C69 2; C147 1; C148 1 2; C152 2; C159 1; C160 1 2; C163 2; C183 1; C184 1 2; C189 2; C195 1; C196 1 2; C199 2; C207 1; C208 1 2; C211 2; C219 1; C220 1 2; C223 2; C231 1; C232 1 2; C237 2; C243 1; C244 1 2; C249 2; LED11 1(CATHODE); LED18 1(CATHODE); LED19 1(CATHODE); LED21 1(CATHODE); LED22 1(CATHODE); LED23 1(CATHODE); LED24 1(CATHODE); LED25 1(CATHODE); LED26 1(CATHODE); R91 1 2; R92 1; R93 1 2; R94 2; R95 1 2; R96 1 2; R97 1; R98 1 2; R99 2; R100 1 2; R101 1; R102 1 2; R103 1 2; R104 1; R189 1 2; R190 1; R191 1 2; R192 2; R193 1 2; R194 1 2; R195 1; R196 1 2; R197 2; R198 1 2; R199 1 2; R200 1; R201 1 2; R202 1; R203 1 2; R204 1; R205 1 2; R206 2; R207 1 2; R208 1 2; R209 1; R210 1 2; R211 2; R212 1 2; R213 1; R214 1 2; R215 1 2; R216 1; R231 1 2; R232 1; R233 1 2; R234 2; R235 1 2; R236 1 2; R237 1; R238 1 2; R239 2; R240 1 2; R241 1; R242 1 2; R243 1 2; R244 1; R245 1 2; R246 1; R247 1 2; R248 2; R249 1 2; R250 1 2; R251 1; R252 1 2; R253 2; R254 1 2; R255 1; R256 1 2; R257 1 2; R258 1; R259 1 2; R260 1; R261 1 2; R262 2; R263 1 2; R264 1 2; R265 1; R266 1 2; R267 2; R268 1 2; R269 1; R270 1 2; R271 1 2; R272 1; R273 1 2; R274 1; R275 1 2; R276 2; R277 1 2; R278 1 2; R279 1; R280 1 2; R281 2; R282 1 2; R283 1; R284 1 2; R285 1 2; R286 1; R287 1 2; R288 1; R289 1 2; R290 2; R291 1 2; R292 1 2; R293 1; R294 1 2; R295 2; R296 1 2; R297 1; R298 1 2; R299 1 2; R300 1; R301 1 2; R302 1; R303 1 2; R304 2; R305 1 2; R306 1 2; R307 1; R308 1 2; R309 2; R310 1 2; R311 1; R312 1 2; R313 1 2; R314 1; U25 1(O1) 2(-) 3(+) 6(Out) 8(O2); U26 1(Vin) 3(Out) 6(/EF) 7(CL) 8(-15VA); U27 1(+) 5(FB) 6(Out) 8(-); U46 1(O1) 2(-) 3(+) 6(Out) 8(O2); U47 1(Vin) 3(Out) 6(/EF) 7(CL) 8(-15VA); U48 1(+) 5(FB) 6(Out) 8(-); U49 1(O1) 2(-) 3(+) 6(Out) 8(O2); U50 1(Vin) 3(Out) 6(/EF) 7(CL) 8(-15VA); U51 1(+) 5(FB) 6(Out) 8(-); U55 1(O1) 2(-) 3(+) 6(Out) 8(O2); U56 1(Vin) 3(Out) 6(/EF) 7(CL) 8(-15VA); U57 1(+) 5(FB) 6(Out) 8(-); U58 1(O1) 2(-) 3(+) 6(Out) 8(O2); U59 1(Vin) 3(Out) 6(/EF) 7(CL) 8(-15VA); U60 1(+) 5(FB) 6(Out) 8(-); U61 1(O1) 2(-) 3(+) 6(Out) 8(O2); U62 1(Vin) 3(Out) 6(/EF) 7(CL) 8(-15VA); U63 1(+) 5(FB) 6(Out) 8(-); U64 1(O1) 2(-) 3(+) 6(Out) 8(O2); U65 1(Vin) 3(Out) 6(/EF) 7(CL) 8(-15VA); U66 1(+) 5(FB) 6(Out) 8(-); U67 1(O1) 2(-) 3(+) 6(Out) 8(O2); U68 1(Vin) 3(Out) 6(/EF) 7(CL) 8(-15VA); U69 1(+) 5(FB) 6(Out) 8(-); U70 1(O1) 2(-) 3(+) 6(Out) 8(O2); U71 1(Vin) 3(Out) 6(/EF) 7(CL) 8(-15VA); U72 1(+) 5(FB) 6(Out) 8(-)

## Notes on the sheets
sheet 13
- Vin: 0,5 a 4,5V
  M: -12,5 a +12,5mAef
sheet 14
- Vin: 0,5 a 4,5V
  M: -12,5 a +12,5mAef
sheet 15
- Vin: 0,5 a 4,5V
  M: -250 a +250mA
sheet 16
- Vin: 0,5 a 4,5V
  M: -50 a +50mA
sheet 17
- Vin: 0,5 a 4,5V
  M: -50 a +50mA
sheet 19
- Vin: 0,5 a 4,5V
  M: -50 a +50mA
sheet 20
- Vin: 0,5 a 4,5V
  M: -12,5 a +12,5mAef
sheet 21
- Vin: 0,5 a 4,5V
  M: -250 a +250mA
sheet 22
- Vin: 0,5 a 4,5V
  M: -250 a +250mA
